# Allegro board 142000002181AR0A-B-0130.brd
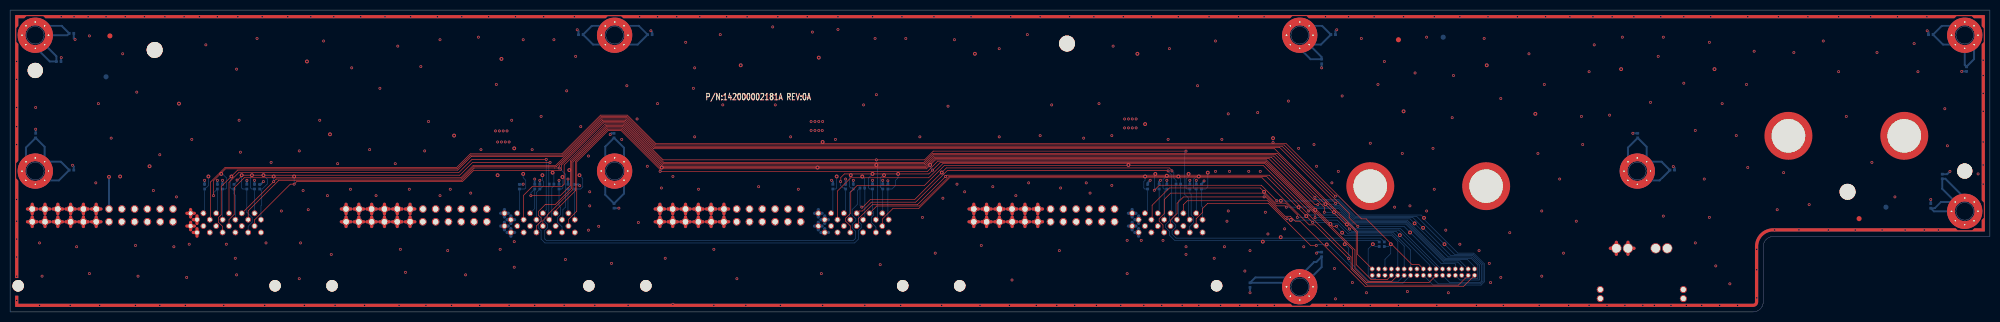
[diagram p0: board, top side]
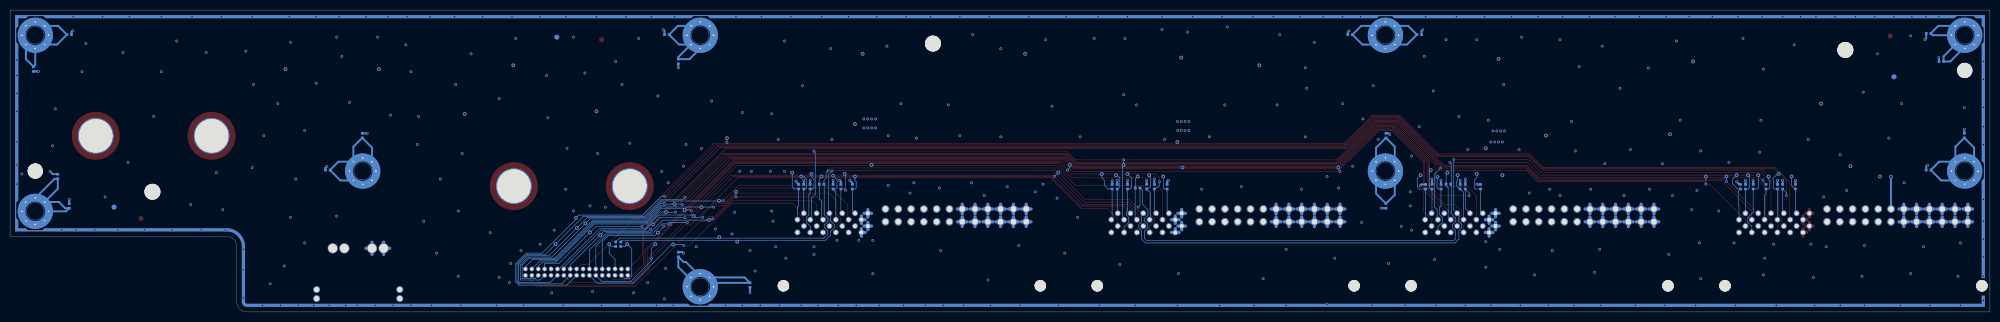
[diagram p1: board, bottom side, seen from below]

Outline 393 x 60 mm; copper layers: TOP, G2, V3, G4, V5, G6, V7, G8, V9, G10, V11, V12, G13, V14, G15, V16, G17, V18, G19, V20, G21, BOTTOM. Coordinates in mm from the lower left corner of the outline.

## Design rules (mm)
net group CLS_GND: nets GND_1 GND_2 GND_3 GND_4 GND_5 GND_6 GND_7 GND_8 GND_9
net group CLS_I2C: nets MB_PDU_SCL_R MB_PDU_SDA_R PDU_SCL PDU_SDA

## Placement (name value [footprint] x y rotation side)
C1  1000pF/50V  [CC0402]  12.19 55.37 270 bottom
C2  1000pF/50V  [CC0402]  113.28 55.12 90 bottom
C3  1000pF/50V  [CC0402]  127 55.12 270 bottom
C4  1000pF/50V  [CC0402]  262.64 55.12 270 bottom
C5  1000pF/50V  [CC0402]  381.25 55.12 90 bottom
C6  1000pF/50V  [CC0402]  9.65 49.78 270 bottom
C7  1000pF/50V  [CC0402]  260.35 49.78 180 bottom
C8  1000pF/50V  [CC0402]  388.37 48.26 180 bottom
C9  1000pF/50V  [CC0402]  5.08 35.05 0 bottom
C10  1000pF/50V  [CC0402]  119.89 35.05 0 bottom
C11  1000pF/50V  [CC0402]  323.09 35.05 0 bottom
C12  1000pF/50V  [CC0402]  12.19 28.19 270 bottom
C13  1000pF/50V  [CC0402]  329.95 28.19 270 bottom
C14  1000pF/50V  [CC0402]  383.54 26.92 0 bottom
C15  1000pF/50V  [CC0402]  119.89 21.08 180 bottom
C16  1000pF/50V  [CC0402]  381.25 21.08 0 bottom
C17  1000pF/50V  [CC0402]  260.35 11.43 0 bottom
C18  1000pF/50V  [CC0402]  246.13 5.33 180 bottom
CONN1  HI POWER  [CONN_2D54_48DP_54D25W_PIP_1]  27.1 5.2 180 bottom
CONN2  HI POWER  [CONN_2D54_48DP_54D25W_PIP_1]  89.4 5.2 180 bottom
CONN3  HI POWER  [CONN_2D54_48DP_54D25W_PIP_1]  151.7 5.2 180 bottom
CONN4  HI POWER  [CONN_2D54_48DP_54D25W_PIP_1]  214 5.2 180 bottom
CONN5  CONN_POWER_4P_G4  [CONN_2D3_4DP_18D2W12D3L_PIP]  323.9 12.65 0 bottom
CONN6  LCB25-G3424H01R-08  [CONN_1D27_2X17DP_90DEG_PIP]  280.54 7.9 0 bottom
H1  *SCREW_8_1  [MTH_276C138D_8DP]  5 55 0 top
H2  *SCREW_8_1  [MTH_276C138D_8DP]  120 55 0 top
H3  *SCREW_8_1  [MTH_276C138D_8DP]  256 55 0 top
H4  *SCREW_8_1  [MTH_276C138D_8DP]  388 55 0 top
H5  *SCREW_8_1  [MTH_276C138D_8DP]  5 28 0 top
H6  *SCREW_8_1  [MTH_276C138D_8DP]  120 28 0 top
H7  *SCREW_8_1  [MTH_276C138D_8DP]  323 28 0 top
H8  *SCREW_8_1  [MTH_276C138D_8DP]  388 20 0 top
H9  *SCREW_8_1  [MTH_276C138D_8DP]  256 5 0 top
NOREF  -  []  63.91 5.2 0 top
NOREF#2  -  []  270 25 0 top
NOREF#3  -  [unnamed#2]  275.59 54.1 0 top
NOREF#4  -  []  256 5 0 top
NOREF#5  -  []  388 20 0 top
NOREF#6  -  [unnamed#2]  367.03 18.54 0 top
NOREF#7  -  []  120 55 0 top
NOREF#8  -  [unnamed#2]  388 28 0 top
NOREF#9  -  []  388 55 0 top
NOREF#10  -  []  376 35 0 top
NOREF#11  -  []  353 35 0 top
NOREF#12  -  []  0 0 0 top
NOREF#13  -  []  393 15 0 top
NOREF#14  -  []  270 25 0 top
NOREF#15  -  []  293 25 0 top
NOREF#16  -  []  126.2 5.2 0 top
NOREF#17  -  []  5 48 0 top
NOREF#18  -  []  5 55 0 top
NOREF#19  -  []  323 28 0 top
NOREF#20  -  []  120 55 0 top
NOREF#21  -  []  388 55 0 top
NOREF#22  -  []  139.45 45.21 0 top
NOREF#23  -  []  1.61 5.2 0 top
NOREF#24  -  []  323 28 0 top
NOREF#25  -  []  256 55 0 top
NOREF#26  -  [unnamed#2]  364.74 23.88 0 top
NOREF#27  -  [unnamed#2]  5 48 0 top
NOREF#28  -  []  270.38 8.54 0 top
NOREF#29  -  [unnamed#2]  28.7 52.07 0 top
NOREF#30  -  []  0 0 0 top
NOREF#31  -  [unnamed#2]  19.81 54.86 0 top
NOREF#32  -  []  506.73 -44.45 0 top
NOREF#33  -  []  328.95 12.65 0 top
NOREF#34  -  []  0 0 0 top
NOREF#35  -  []  120 28 0 top
NOREF#36  -  []  188.51 5.2 0 top
NOREF#37  -  []  0 60 0 top
NOREF#38  -  []  320.74 -38.48 0 top
NOREF#39  -  []  0 0 0 top
NOREF#40  -  []  353 35 0 top
NOREF#41  -  []  270.38 7.27 0 top
NOREF#42  -  []  1.61 5.2 0 top
NOREF#43  -  [unnamed#2]  209.8 53.34 0 top
NOREF#44  -  []  328.95 12.65 0 top
NOREF#45  -  []  -40.64 -30.48 0 top
NOREF#46  -  [unnamed#2]  372.36 20.83 180 bottom
NOREF#47  -  [unnamed#2]  19.05 46.74 180 bottom
NOREF#48  -  [unnamed#2]  284.48 54.61 180 bottom
R1  33ohm  [RC0402]  107.49 25.4 90 bottom
R2  33ohm  [RC0402]  231.9 25.4 90 bottom
R3  0ohm  [RC0402]  38.61 24.89 180 bottom
R4  1Kohm  [RC0402]  41.15 24.89 180 bottom
R5  0ohm  [RC0402]  42.16 24.89 180 bottom
R6  33ohm  [RC0402]  44.45 24.89 0 bottom
R7  0ohm  [RC0402]  46.99 24.89 0 bottom
R8  0ohm  [RC0402]  48.51 24.89 180 bottom
R9  0ohm  [RC0402]  49.53 24.89 180 bottom
R10  0ohm  [RC0402]  101.09 24.89 180 bottom
R11  1Kohm  [RC0402]  104.14 24.89 180 bottom
R12  0ohm  [RC0402]  105.16 24.89 180 bottom
R13  0ohm  [RC0402]  108.97 24.89 0 bottom
R14  0ohm  [RC0402]  110.74 24.89 180 bottom
R15  0ohm  [RC0402]  112.01 24.89 180 bottom
R16  0ohm  [RC0402]  163.32 24.89 180 bottom
R17  1Kohm  [RC0402]  165.86 24.89 180 bottom
R18  0ohm  [RC0402]  167.39 24.89 180 bottom
R19  0ohm  [RC0402]  171.2 24.89 0 bottom
R20  0ohm  [RC0402]  173.23 24.89 180 bottom
R21  0ohm  [RC0402]  174.24 24.89 180 bottom
R22  0ohm  [RC0402]  225.81 24.89 180 bottom
R23  1Kohm  [RC0402]  228.09 24.89 180 bottom
R24  0ohm  [RC0402]  229.62 24.89 180 bottom
R25  0ohm  [RC0402]  234.19 24.89 0 bottom
R26  0ohm  [RC0402]  235.46 24.89 180 bottom
R27  0ohm  [RC0402]  236.47 24.89 180 bottom
R28  33ohm  [RC0402]  169.16 24.64 90 bottom
R29  0ohm  [RC0402]  271.78 13.46 180 bottom
R30  0ohm  [RC0402]  272.8 13.46 0 bottom
U1_PF  HI POWER  [GUIDE_PIN_1DP_9D53W15D14H]  353 35 0 top
U2_PF  HI POWER  [GUIDE_PIN_1DP_9D53W15D14H]  376 35 0 top
U3_PF  HI POWER  [GUIDE_PIN_1DP_9D53W15D14H]  270 25 0 top
U4_PF  HI POWER  [GUIDE_PIN_1DP_9D53W15D14H]  293 25 0 top

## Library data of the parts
C1-C18 = C_NP
CONN1-CONN4 = CONN_POWER_ALLTOP_DIP48_1
CONN5 = CONN_POWER_4P_G4
CONN6 = PIN HEADER_MALE_17PX2R
H1-H9 = SCREW_8_1
R1-R30 = R: tolerance: 1%
U1_PF U2_PF U3_PF U4_PF = GUIDE PIN_1P

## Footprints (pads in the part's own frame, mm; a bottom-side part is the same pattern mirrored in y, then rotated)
CC0402
  rect 0.559x0.539 smd: 1(0,0.454) 2(0,-0.454)
CONN_1D27_2X17DP_90DEG_PIP
  round 0.94 hole 0.61: 1(-10.16,-0.635) 2(-10.16,0.635) 3(-8.89,-0.635) 4(-8.89,0.635) 5(-7.62,-0.635) 6(-7.62,0.635) 7(-6.35,-0.635) 8(-6.35,0.635) 9(-5.08,-0.635) 10(-5.08,0.635) 11(-3.81,-0.635) 12(-3.81,0.635) 13(-2.54,-0.635) 14(-2.54,0.635) 15(-1.27,-0.635) 16(-1.27,0.635) 17(0,-0.635) 18(0,0.635) 19(1.27,-0.635) 20(1.27,0.635) 21(2.54,-0.635) 22(2.54,0.635) 23(3.81,-0.635) 24(3.81,0.635) 25(5.08,-0.635) 26(5.08,0.635) 27(6.35,-0.635) 28(6.35,0.635) 29(7.62,-0.635) 30(7.62,0.635) 31(8.89,-0.635) 32(8.89,0.635) 33(10.16,-0.635) 34(10.16,0.635)
CONN_2D3_4DP_18D2W12D3L_PIP
  round 1.397 hole 1.016: G1(-8.25,10) G2(-8.25,8.2) G3(8.25,10) G4(8.25,8.2)
  round 2.032 hole 1.702: P1(5.05,0) P2(2.75,0) P3(-2.75,0) P4(-5.05,0)
CONN_2D54_48DP_54D25W_PIP_1
  round 2.286 hole 2.286 unplated: (-25.495,0) (25.495,0)
  round 1.524 hole 1.092: P1-11(-5.235,15.26) P1-12(-2.695,15.26) P1-13(-0.155,15.26) P1-21(2.385,15.26) P1-22(4.925,15.26) P1-23(7.465,15.26) P2-11(10.005,15.26) P2-12(12.545,15.26) P2-13(15.085,15.26) P2-21(17.625,15.26) P2-22(20.165,15.26) P2-23(22.705,15.26) P3-11(-5.235,12.72) P3-12(-2.695,12.72) P3-13(-0.155,12.72) P3-21(2.385,12.72) P3-22(4.925,12.72) P3-23(7.465,12.72) P4-11(10.005,12.72) P4-12(12.545,12.72) P4-13(15.085,12.72) P4-21(17.625,12.72) P4-22(20.165,12.72) P4-23(22.705,12.72)
  round 1.143 hole 0.762: S1(-22.705,13.14) S2(-21.435,14.41) S3(-20.165,13.14) S4(-18.895,14.41) S5(-17.625,13.14) S6(-16.355,14.41) S7(-15.085,13.14) S8(-13.815,14.41) S9(-12.545,13.14) S10(-11.275,14.41) S11(-10.005,13.14) S12(-8.735,14.41) S13(-22.705,10.6) S14(-21.435,11.87) S15(-20.165,10.6) S16(-18.895,11.87) S17(-17.625,10.6) S18(-16.355,11.87) S19(-15.085,10.6) S20(-13.815,11.87) S21(-12.545,10.6) S22(-11.275,11.87) S23(-10.005,10.6) S24(-8.735,11.87)
GUIDE_PIN_1DP_9D53W15D14H
  round 9.525 hole 6.629: 1(0,0)
MTH_276C138D_8DP
  round 0 hole 3.505 unplated: (0,0)
  custom 0.407x0.407 hole 0.305: 1(0,2.629) 3(2.629,0) 5(0,-2.629) 7(-2.629,0)
  custom 0.407x0.407 hole 0.305 rot 135: 2(1.859,1.859) 6(-1.859,-1.859)
  custom 0.407x0.407 hole 0.305 rot 45: 4(1.859,-1.859) 8(-1.859,1.859)
RC0402
  rect 0.559x0.539 smd: 1(0,0.454) 2(0,-0.454)
unnamed#2
  round 1.016 smd: (0,0)

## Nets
GND: C1.2 C2.2 C3.2 C4.2 C5.2 C6.2 C7.2 C8.2 C9.2 C10.2 C11.2 C12.2 C13.2 C14.2 C15.2 C16.2 C17.2 C18.2 CONN1.P2-11 CONN1.P2-12 CONN1.P2-13 CONN1.P2-21 CONN1.P2-22 CONN1.P2-23 CONN1.P4-11 CONN1.P4-12 CONN1.P4-13 CONN1.P4-21 CONN1.P4-22 CONN1.P4-23 CONN2.P2-11 CONN2.P2-12 CONN2.P2-13 CONN2.P2-21 CONN2.P2-22 CONN2.P2-23 CONN2.P4-11 CONN2.P4-12 CONN2.P4-13 CONN2.P4-21 CONN2.P4-22 CONN2.P4-23 CONN3.P2-11 CONN3.P2-12 CONN3.P2-13 CONN3.P2-21 CONN3.P2-22 CONN3.P2-23 CONN3.P4-11 CONN3.P4-12 CONN3.P4-13 CONN3.P4-21 CONN3.P4-22 CONN3.P4-23 CONN4.P2-11 CONN4.P2-12 CONN4.P2-13 CONN4.P2-21 CONN4.P2-22 CONN4.P2-23 CONN4.P4-11 CONN4.P4-12 CONN4.P4-13 CONN4.P4-21 CONN4.P4-22 CONN4.P4-23 CONN5.P3(POWER_1N) CONN5.P4(POWER_2N) CONN6.2 CONN6.3 CONN6.6 CONN6.7 CONN6.15 CONN6.16 CONN6.25 CONN6.26 R3.1 R4.1 R5.1 R7.2 R8.1 R10.1 R11.1 R12.1 R13.2 R14.1 R16.1 R17.1 R18.1 R19.2 R20.1 R22.1 R23.1 R24.1 R25.2 R26.1 U2_PF.1 U4_PF.1
GND_1: C1.1 C6.1 H1.1 H1.2 H1.3 H1.4 H1.5 H1.6 H1.7 H1.8
GND_2: C9.1 C12.1 H5.1 H5.2 H5.3 H5.4 H5.5 H5.6 H5.7 H5.8
GND_3: C2.1 C3.1 H2.1 H2.2 H2.3 H2.4 H2.5 H2.6 H2.7 H2.8
GND_4: C11.1 C13.1 H7.1 H7.2 H7.3 H7.4 H7.5 H7.6 H7.7 H7.8
GND_5: C10.1 C15.1 H6.1 H6.2 H6.3 H6.4 H6.5 H6.6 H6.7 H6.8
GND_6: C4.1 C7.1 H3.1 H3.2 H3.3 H3.4 H3.5 H3.6 H3.7 H3.8
GND_7: C17.1 C18.1 H9.1 H9.2 H9.3 H9.4 H9.5 H9.6 H9.7 H9.8
GND_8: C14.1 C16.1 H8.1 H8.2 H8.3 H8.4 H8.5 H8.6 H8.7 H8.8
GND_9: C5.1 C8.1 H4.1 H4.2 H4.3 H4.4 H4.5 H4.6 H4.7 H4.8
MB_PDU_SCL_R: CONN6.4 R29.2
MB_PDU_SDA_R: CONN6.5 R30.1
PDU_12V: CONN1.P1-11 CONN1.P1-12 CONN1.P1-13 CONN1.P1-21 CONN1.P1-22 CONN1.P1-23 CONN1.P3-11 CONN1.P3-12 CONN1.P3-13 CONN1.P3-21 CONN1.P3-22 CONN1.P3-23 CONN2.P1-11 CONN2.P1-12 CONN2.P1-13 CONN2.P1-21 CONN2.P1-22 CONN2.P1-23 CONN2.P3-11 CONN2.P3-12 CONN2.P3-13 CONN2.P3-21 CONN2.P3-22 CONN2.P3-23 CONN3.P1-11 CONN3.P1-12 CONN3.P1-13 CONN3.P1-21 CONN3.P1-22 CONN3.P1-23 CONN3.P3-11 CONN3.P3-12 CONN3.P3-13 CONN3.P3-21 CONN3.P3-22 CONN3.P3-23 CONN4.P1-11 CONN4.P1-12 CONN4.P1-13 CONN4.P1-21 CONN4.P1-22 CONN4.P1-23 CONN4.P3-11 CONN4.P3-12 CONN4.P3-13 CONN4.P3-21 CONN4.P3-22 CONN4.P3-23 CONN5.P1(POWER_1P) CONN5.P2(POWER_2P) R9.1 R15.1 R21.1 R27.1 U1_PF.1 U3_PF.1
PDU_ISHARE: CONN1.S3 CONN2.S3 CONN3.S3 CONN4.S3
PDU_SCL: CONN1.S6 CONN2.S6 CONN3.S6 CONN4.S6 R29.1
PDU_SDA: R1.2 R2.2 R6.2 R28.2 R30.2
PS1_A0: CONN1.S15 R7.1
PS1_A1: CONN1.S10 R3.2
PS2_A0: CONN2.S15 R13.1
PS2_A1: CONN2.S10 R10.2
PS3_A0: CONN3.S15 R19.1
PS3_A1: CONN3.S10 R16.2
PS4_A0: CONN4.S15 R25.1
PS4_A1: CONN4.S10 R22.2
PSU1_12V_SENSE: CONN1.S1 R9.2
PSU1_ACOK_H: CONN1.S19 CONN6.27
PSU1_EEPROM_WP: CONN1.S18 CONN6.28
PSU1_PRESENT_L: CONN1.S14 CONN6.8
PSU1_PSKILL: CONN1.S7 R5.2
PSU1_PSON_L: CONN1.S8 CONN6.18 R4.2
PSU1_PWOK_H: CONN1.S9 CONN6.17
PSU1_RTN_SENSE: CONN1.S2 R8.2
PSU1_SDA: CONN1.S5 R6.1
PSU1_SMB_ALERT_L: CONN1.S4 CONN6.1
PSU2_12V_SENSE: CONN2.S1 R15.2
PSU2_ACOK_H: CONN2.S19 CONN6.29
PSU2_EEPROM_WP: CONN2.S18 CONN6.30
PSU2_PRESENT_L: CONN2.S14 CONN6.10
PSU2_PSKILL: CONN2.S7 R12.2
PSU2_PSON_L: CONN2.S8 CONN6.20 R11.2
PSU2_PWOK_H: CONN2.S9 CONN6.19
PSU2_RTN_SENSE: CONN2.S2 R14.2
PSU2_SDA: CONN2.S5 R1.1
PSU2_SMB_ALERT_L: CONN2.S4 CONN6.9
PSU3_12V_SENSE: CONN3.S1 R21.2
PSU3_ACOK_H: CONN3.S19 CONN6.31
PSU3_EEPROM_WP: CONN3.S18 CONN6.32
PSU3_PRESENT_L: CONN3.S14 CONN6.12
PSU3_PSKILL: CONN3.S7 R18.2
PSU3_PSON_L: CONN3.S8 CONN6.22 R17.2
PSU3_PWOK_H: CONN3.S9 CONN6.21
PSU3_RTN_SENSE: CONN3.S2 R20.2
PSU3_SDA: CONN3.S5 R28.1
PSU3_SMB_ALERT_L: CONN3.S4 CONN6.11
PSU4_12V_SENSE: CONN4.S1 R27.2
PSU4_ACOK_H: CONN4.S19 CONN6.33
PSU4_EEPROM_WP: CONN4.S18 CONN6.34
PSU4_PRESENT_L: CONN4.S14 CONN6.14
PSU4_PSKILL: CONN4.S7 R24.2
PSU4_PSON_L: CONN4.S8 CONN6.24 R23.2
PSU4_PWOK_H: CONN4.S9 CONN6.23
PSU4_RTN_SENSE: CONN4.S2 R26.2
PSU4_SDA: CONN4.S5 R2.1
PSU4_SMB_ALERT_L: CONN4.S4 CONN6.13
PSU_VSTB_3V3: CONN1.S11 CONN1.S12 CONN1.S23 CONN1.S24 CONN2.S11 CONN2.S12 CONN2.S23 CONN2.S24 CONN3.S11 CONN3.S12 CONN3.S23 CONN3.S24 CONN4.S11 CONN4.S12 CONN4.S23 CONN4.S24

Pads without a net: CONN1 S13 S16 S17 S20 S21 S22; CONN2 S13 S16 S17 S20 S21 S22; CONN3 S13 S16 S17 S20 S21 S22; CONN4 S13 S16 S17 S20 S21 S22; CONN5 G1 G2 G3 G4

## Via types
v1: diameter 0.762, hole 0.381, TOP to BOTTOM, 78 vias
v2: diameter 0.559, hole 0.305, TOP to BOTTOM, 513 vias

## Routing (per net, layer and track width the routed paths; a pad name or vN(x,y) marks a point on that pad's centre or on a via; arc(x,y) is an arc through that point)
GND: length 2287.9
  TOP w0.635: CONN2.P4-21 72.72,17.92 ; CONN2.P4-21 71.78,16.98 ; CONN2.P4-21 70.83,17.92 ; CONN2.P4-21 71.78,18.86 ; CONN4.P4-12 201.46,18.86 ; CONN4.P4-12 201.46,16.98 ; CONN4.P4-12 200.51,17.92 ; CONN4.P4-12 202.4,17.92 ; CONN3.P4-11 141.69,18.86 ; CONN3.P4-11 141.69,16.98 ; CONN3.P4-11 142.64,17.92 ; CONN3.P4-11 140.75,17.92 ; CONN2.P2-21 71.78,21.4 ; CONN2.P2-21 71.78,19.52 ; CONN2.P2-21 70.83,20.46 ; CONN2.P2-21 72.72,20.46 ; CONN4.P4-11 204,18.86 ; CONN4.P4-11 204,16.98 ; CONN4.P4-11 204.94,17.92 ; CONN4.P4-11 203.05,17.92 ; CONN4.P2-13 198.92,21.4 ; CONN4.P2-13 199.86,20.46 ; CONN4.P2-13 197.97,20.46 ; CONN4.P2-13 198.92,19.52 ; 192.89,20.46 CONN4.P2-22 ; CONN4.P2-22 193.84,21.4 ; CONN4.P2-22 194.78,20.46 ; CONN4.P2-22 193.84,19.52 ; 317.66,12.65 CONN5.P4 ; CONN5.P4 318.85,11.46 ; CONN5.P4 318.85,13.84 ; CONN3.P2-11 141.69,21.4 ; CONN3.P2-11 142.64,20.46 ; CONN3.P2-11 141.69,19.52 ; CONN3.P2-11 140.75,20.46 ; 8.53,17.92 CONN1.P4-21 ; CONN1.P4-21 9.47,16.98 ; CONN1.P4-21 9.47,18.86 ; CONN1.P4-21 10.42,17.92 ; 133.13,20.46 CONN3.P2-21 ; CONN3.P2-21 134.07,21.4 ; CONN3.P2-21 134.07,19.52 ; CONN3.P2-21 135.02,20.46 ; CONN2.P2-23 66.7,21.4 ; CONN2.P2-23 66.7,19.52 ; CONN2.P2-23 65.75,20.46 ; CONN2.P2-23 67.64,20.46 ; 65.75,17.92 CONN2.P4-23 ; CONN2.P4-23 66.7,16.98 ; CONN2.P4-23 67.64,17.92 ; CONN2.P4-23 66.7,18.86 ; CONN4.P4-22 193.84,18.86 ; CONN4.P4-22 194.78,17.92 ; CONN4.P4-22 192.89,17.92 ; CONN4.P4-22 193.84,16.98 ; CONN3.P2-12 140.1,20.46 ; CONN3.P2-12 138.21,20.46 ; CONN3.P2-12 139.15,21.4 ; CONN3.P2-12 139.15,19.52 ; 130.59,17.92 CONN3.P4-22 ; CONN3.P4-22 132.48,17.92 ; CONN3.P4-22 131.53,16.98 ; CONN3.P4-22 131.53,18.86 ; 4.39,16.98 CONN1.P4-23 ; CONN1.P4-23 5.34,17.92 ; CONN1.P4-23 4.39,18.86 ; CONN1.P4-23 3.45,17.92 ; 12.01,19.52 CONN1.P2-13 ; CONN1.P2-13 11.07,20.46 ; CONN1.P2-13 12.01,21.4 ; CONN1.P2-13 12.96,20.46 ; 128.05,20.46 CONN3.P2-23 ; CONN3.P2-23 128.99,19.52 ; CONN3.P2-23 129.94,20.46 ; CONN3.P2-23 128.99,21.4 ; CONN2.P2-12 76.86,21.4 ; CONN2.P2-12 77.8,20.46 ; CONN2.P2-12 76.86,19.52 ; CONN2.P2-12 75.91,20.46 ; CONN1.P2-21 9.47,21.4 ; CONN1.P2-21 8.53,20.46 ; CONN1.P2-21 9.47,19.52 ; CONN1.P2-21 10.42,20.46 ; CONN3.P2-13 136.61,21.4 ; CONN3.P2-13 135.67,20.46 ; CONN3.P2-13 136.61,19.52 ; CONN3.P2-13 137.56,20.46 ; CONN3.P4-21 135.02,17.92 ; CONN3.P4-21 134.07,16.98 ; CONN3.P4-21 134.07,18.86 ; CONN3.P4-21 133.13,17.92 ; 191.3,19.52 CONN4.P2-23 ; CONN4.P2-23 192.24,20.46 ; CONN4.P2-23 191.3,21.4 ; CONN4.P2-23 190.35,20.46 ; CONN4.P2-12 202.4,20.46 ; CONN4.P2-12 201.46,19.52 ; CONN4.P2-12 200.51,20.46 ; CONN4.P2-12 201.46,21.4 ; 195.43,20.46 CONN4.P2-21 ; CONN4.P2-21 197.32,20.46 ; CONN4.P2-21 196.38,19.52 ; CONN4.P2-21 196.38,21.4 ; 128.99,16.98 CONN3.P4-23 ; CONN3.P4-23 128.05,17.92 ; CONN3.P4-23 128.99,18.86 ; CONN3.P4-23 129.94,17.92 ; 74.32,19.52 CONN2.P2-13 ; CONN2.P2-13 74.32,21.4 ; CONN2.P2-13 73.37,20.46 ; CONN2.P2-13 75.26,20.46 ; CONN2.P4-13 74.32,18.86 ; CONN2.P4-13 75.26,17.92 ; CONN2.P4-13 74.32,16.98 ; CONN2.P4-13 73.37,17.92 ; 14.55,16.98 CONN1.P4-12 ; CONN1.P4-12 13.61,17.92 ; CONN1.P4-12 14.55,18.86 ; CONN1.P4-12 15.5,17.92 ; CONN4.P2-11 204.94,20.46 ; CONN4.P2-11 204,21.4 ; CONN4.P2-11 203.05,20.46 ; CONN4.P2-11 204,19.52 ; 69.24,19.52 CONN2.P2-22 ; CONN2.P2-22 68.29,20.46 ; CONN2.P2-22 70.18,20.46 ; CONN2.P2-22 69.24,21.4 ; CONN3.P2-22 132.48,20.46 ; CONN3.P2-22 131.53,21.4 ; CONN3.P2-22 131.53,19.52 ; CONN3.P2-22 130.59,20.46 ; 195.43,17.92 CONN4.P4-21 ; CONN4.P4-21 196.38,16.98 ; CONN4.P4-21 197.32,17.92 ; CONN4.P4-21 196.38,18.86 ; CONN4.P4-23 191.3,18.86 ; CONN4.P4-23 191.3,16.98 ; CONN4.P4-23 192.24,17.92 ; CONN4.P4-23 190.35,17.92 ; 12.01,16.98 CONN1.P4-13 ; CONN1.P4-13 12.01,18.86 ; CONN1.P4-13 11.07,17.92 ; CONN1.P4-13 12.96,17.92 ; CONN2.P4-11 80.34,17.92 ; CONN2.P4-11 79.4,18.86 ; CONN2.P4-11 78.45,17.92 ; CONN2.P4-11 79.4,16.98 ; CONN3.P4-12 139.15,18.86 ; CONN3.P4-12 138.21,17.92 ; CONN3.P4-12 140.1,17.92 ; CONN3.P4-12 139.15,16.98 ; 135.67,17.92 CONN3.P4-13 ; CONN3.P4-13 137.56,17.92 ; CONN3.P4-13 136.61,18.86 ; CONN3.P4-13 136.61,16.98 ; 4.39,19.52 CONN1.P2-23 ; CONN1.P2-23 3.45,20.46 ; CONN1.P2-23 4.39,21.4 ; CONN1.P2-23 5.34,20.46 ; 6.93,19.52 CONN1.P2-22 ; CONN1.P2-22 7.88,20.46 ; CONN1.P2-22 6.93,21.4 ; CONN1.P2-22 5.99,20.46 ; CONN2.P2-11 80.34,20.46 ; CONN2.P2-11 79.4,19.52 ; CONN2.P2-11 78.45,20.46 ; CONN2.P2-11 79.4,21.4 ; 321.15,11.46 CONN5.P3 ; CONN5.P3 321.15,13.84 ; CONN5.P3 322.34,12.65 ; 69.24,16.98 CONN2.P4-22 ; CONN2.P4-22 68.29,17.92 ; CONN2.P4-22 70.18,17.92 ; CONN2.P4-22 69.24,18.86 ; 5.99,17.92 CONN1.P4-22 ; CONN1.P4-22 6.93,18.86 ; CONN1.P4-22 7.88,17.92 ; CONN1.P4-22 6.93,16.98 ; 14.55,19.52 CONN1.P2-12 ; CONN1.P2-12 14.55,21.4 ; CONN1.P2-12 13.61,20.46 ; CONN1.P2-12 15.5,20.46 ; 76.86,16.98 CONN2.P4-12 ; CONN2.P4-12 77.8,17.92 ; CONN2.P4-12 76.86,18.86 ; CONN2.P4-12 75.91,17.92 ; 197.97,17.92 CONN4.P4-13 ; CONN4.P4-13 198.92,16.98 ; CONN4.P4-13 198.92,18.86 ; CONN4.P4-13 199.86,17.92 ; CONN1.P2-11 17.09,21.4 ; CONN1.P2-11 18.04,20.46 ; CONN1.P2-11 16.15,20.46 ; CONN1.P2-11 17.09,19.52 ; CONN1.P4-11 17.09,18.86 ; CONN1.P4-11 16.15,17.92 ; CONN1.P4-11 17.09,16.98 ; CONN1.P4-11 18.04,17.92
  G2 w0.635: CONN1.P4-23 4.39,18.86 ; CONN1.P4-23 3.45,17.92 ; CONN1.P4-23 5.34,17.92 ; CONN1.P4-23 4.39,16.98 ; CONN2.P4-12 77.8,17.92 ; CONN2.P4-12 76.86,18.86 ; CONN2.P4-12 75.91,17.92 ; CONN2.P4-12 76.86,16.98 ; CONN3.P2-11 142.64,20.46 ; CONN3.P2-11 141.69,19.52 ; CONN3.P2-11 140.75,20.46 ; CONN3.P2-11 141.69,21.4 ; CONN1.P2-12 15.5,20.46 ; CONN1.P2-12 14.55,19.52 ; CONN1.P2-12 14.55,21.4 ; CONN1.P2-12 13.61,20.46 ; 4.39,19.52 CONN1.P2-23 ; CONN1.P2-23 5.34,20.46 ; CONN1.P2-23 3.45,20.46 ; CONN1.P2-23 4.39,21.4 ; CONN1.P2-11 17.09,21.4 ; CONN1.P2-11 17.09,19.52 ; CONN1.P2-11 18.04,20.46 ; CONN1.P2-11 16.15,20.46 ; 71.78,16.98 CONN2.P4-21 ; CONN2.P4-21 72.72,17.92 ; CONN2.P4-21 70.83,17.92 ; CONN2.P4-21 71.78,18.86 ; 130.59,17.92 CONN3.P4-22 ; CONN3.P4-22 132.48,17.92 ; CONN3.P4-22 131.53,16.98 ; CONN3.P4-22 131.53,18.86 ; 198.92,16.98 CONN4.P4-13 ; CONN4.P4-13 198.92,18.86 ; CONN4.P4-13 199.86,17.92 ; CONN4.P4-13 197.97,17.92 ; 8.53,20.46 CONN1.P2-21 ; CONN1.P2-21 10.42,20.46 ; CONN1.P2-21 9.47,19.52 ; CONN1.P2-21 9.47,21.4 ; 5.99,17.92 CONN1.P4-22 ; CONN1.P4-22 7.88,17.92 ; CONN1.P4-22 6.93,16.98 ; CONN1.P4-22 6.93,18.86 ; CONN3.P2-23 128.99,21.4 ; CONN3.P2-23 128.05,20.46 ; CONN3.P2-23 128.99,19.52 ; CONN3.P2-23 129.94,20.46 ; 69.24,16.98 CONN2.P4-22 ; CONN2.P4-22 69.24,18.86 ; CONN2.P4-22 68.29,17.92 ; CONN2.P4-22 70.18,17.92 ; CONN4.P2-13 199.86,20.46 ; CONN4.P2-13 198.92,21.4 ; CONN4.P2-13 197.97,20.46 ; CONN4.P2-13 198.92,19.52 ; CONN1.P2-22 6.93,21.4 ; CONN1.P2-22 5.99,20.46 ; CONN1.P2-22 6.93,19.52 ; CONN1.P2-22 7.88,20.46 ; 73.37,17.92 CONN2.P4-13 ; CONN2.P4-13 74.32,18.86 ; CONN2.P4-13 75.26,17.92 ; CONN2.P4-13 74.32,16.98 ; 9.47,16.98 CONN1.P4-21 ; CONN1.P4-21 8.53,17.92 ; CONN1.P4-21 9.47,18.86 ; CONN1.P4-21 10.42,17.92 ; CONN4.P4-11 204.94,17.92 ; CONN4.P4-11 204,18.86 ; CONN4.P4-11 204,16.98 ; CONN4.P4-11 203.05,17.92 ; 195.43,17.92 CONN4.P4-21 ; CONN4.P4-21 196.38,16.98 ; CONN4.P4-21 196.38,18.86 ; CONN4.P4-21 197.32,17.92 ; CONN3.P2-21 135.02,20.46 ; CONN3.P2-21 133.13,20.46 ; CONN3.P2-21 134.07,21.4 ; CONN3.P2-21 134.07,19.52 ; 14.55,16.98 CONN1.P4-12 ; CONN1.P4-12 14.55,18.86 ; CONN1.P4-12 13.61,17.92 ; CONN1.P4-12 15.5,17.92 ; CONN3.P4-11 141.69,18.86 ; CONN3.P4-11 141.69,16.98 ; CONN3.P4-11 140.75,17.92 ; CONN3.P4-11 142.64,17.92 ; CONN4.P4-12 202.4,17.92 ; CONN4.P4-12 200.51,17.92 ; CONN4.P4-12 201.46,16.98 ; CONN4.P4-12 201.46,18.86 ; CONN2.P4-23 66.7,18.86 ; CONN2.P4-23 66.7,16.98 ; CONN2.P4-23 67.64,17.92 ; CONN2.P4-23 65.75,17.92 ; CONN2.P2-11 79.4,21.4 ; CONN2.P2-11 78.45,20.46 ; CONN2.P2-11 80.34,20.46 ; CONN2.P2-11 79.4,19.52 ; CONN2.P2-13 74.32,21.4 ; CONN2.P2-13 73.37,20.46 ; CONN2.P2-13 74.32,19.52 ; CONN2.P2-13 75.26,20.46 ; 11.07,20.46 CONN1.P2-13 ; CONN1.P2-13 12.96,20.46 ; CONN1.P2-13 12.01,19.52 ; CONN1.P2-13 12.01,21.4 ; 204,19.52 CONN4.P2-11 ; CONN4.P2-11 204,21.4 ; CONN4.P2-11 204.94,20.46 ; CONN4.P2-11 203.05,20.46 ; CONN4.P2-21 197.32,20.46 ; CONN4.P2-21 196.38,21.4 ; CONN4.P2-21 195.43,20.46 ; CONN4.P2-21 196.38,19.52 ; 128.99,16.98 CONN3.P4-23 ; CONN3.P4-23 128.05,17.92 ; CONN3.P4-23 129.94,17.92 ; CONN3.P4-23 128.99,18.86 ; 192.89,20.46 CONN4.P2-22 ; CONN4.P2-22 193.84,21.4 ; CONN4.P2-22 194.78,20.46 ; CONN4.P2-22 193.84,19.52 ; 65.75,20.46 CONN2.P2-23 ; CONN2.P2-23 66.7,19.52 ; CONN2.P2-23 66.7,21.4 ; CONN2.P2-23 67.64,20.46 ; 75.91,20.46 CONN2.P2-12 ; CONN2.P2-12 77.8,20.46 ; CONN2.P2-12 76.86,19.52 ; CONN2.P2-12 76.86,21.4 ; CONN4.P4-23 192.24,17.92 ; CONN4.P4-23 191.3,18.86 ; CONN4.P4-23 191.3,16.98 ; CONN4.P4-23 190.35,17.92 ; CONN4.P2-23 191.3,21.4 ; CONN4.P2-23 192.24,20.46 ; CONN4.P2-23 191.3,19.52 ; CONN4.P2-23 190.35,20.46 ; CONN3.P4-12 139.15,18.86 ; CONN3.P4-12 139.15,16.98 ; CONN3.P4-12 138.21,17.92 ; CONN3.P4-12 140.1,17.92 ; 318.85,11.46 CONN5.P4 ; CONN5.P4 317.66,12.65 ; CONN5.P4 318.85,13.84 ; CONN5.P3 321.15,13.84 ; CONN5.P3 321.15,11.46 ; CONN5.P3 322.34,12.65 ; CONN4.P2-12 202.4,20.46 ; CONN4.P2-12 200.51,20.46 ; CONN4.P2-12 201.46,19.52 ; CONN4.P2-12 201.46,21.4 ; 136.61,16.98 CONN3.P4-13 ; CONN3.P4-13 137.56,17.92 ; CONN3.P4-13 136.61,18.86 ; CONN3.P4-13 135.67,17.92 ; 134.07,16.98 CONN3.P4-21 ; CONN3.P4-21 134.07,18.86 ; CONN3.P4-21 135.02,17.92 ; CONN3.P4-21 133.13,17.92 ; 12.01,16.98 CONN1.P4-13 ; CONN1.P4-13 12.01,18.86 ; CONN1.P4-13 12.96,17.92 ; CONN1.P4-13 11.07,17.92 ; 192.89,17.92 CONN4.P4-22 ; CONN4.P4-22 193.84,16.98 ; CONN4.P4-22 194.78,17.92 ; CONN4.P4-22 193.84,18.86 ; CONN3.P2-12 140.1,20.46 ; CONN3.P2-12 139.15,21.4 ; CONN3.P2-12 139.15,19.52 ; CONN3.P2-12 138.21,20.46 ; 17.09,16.98 CONN1.P4-11 ; CONN1.P4-11 18.04,17.92 ; CONN1.P4-11 16.15,17.92 ; CONN1.P4-11 17.09,18.86 ; 78.45,17.92 CONN2.P4-11 ; CONN2.P4-11 80.34,17.92 ; CONN2.P4-11 79.4,18.86 ; CONN2.P4-11 79.4,16.98 ; 136.61,19.52 CONN3.P2-13 ; CONN3.P2-13 136.61,21.4 ; CONN3.P2-13 135.67,20.46 ; CONN3.P2-13 137.56,20.46 ; 130.59,20.46 CONN3.P2-22 ; CONN3.P2-22 131.53,21.4 ; CONN3.P2-22 132.48,20.46 ; CONN3.P2-22 131.53,19.52 ; 70.83,20.46 CONN2.P2-21 ; CONN2.P2-21 72.72,20.46 ; CONN2.P2-21 71.78,21.4 ; CONN2.P2-21 71.78,19.52 ; CONN2.P2-22 70.18,20.46 ; CONN2.P2-22 69.24,19.52 ; CONN2.P2-22 68.29,20.46 ; CONN2.P2-22 69.24,21.4
  G4 w0.635: CONN3.P2-22 131.53,21.4 ; CONN3.P2-22 131.53,19.52 ; CONN3.P2-22 132.48,20.46 ; CONN3.P2-22 130.59,20.46 ; 13.61,17.92 CONN1.P4-12 ; CONN1.P4-12 14.55,16.98 ; CONN1.P4-12 14.55,18.86 ; CONN1.P4-12 15.5,17.92 ; CONN1.P4-13 12.01,18.86 ; CONN1.P4-13 12.96,17.92 ; CONN1.P4-13 11.07,17.92 ; CONN1.P4-13 12.01,16.98 ; CONN3.P4-11 141.69,18.86 ; CONN3.P4-11 142.64,17.92 ; CONN3.P4-11 140.75,17.92 ; CONN3.P4-11 141.69,16.98 ; 6.93,16.98 CONN1.P4-22 ; CONN1.P4-22 6.93,18.86 ; CONN1.P4-22 7.88,17.92 ; CONN1.P4-22 5.99,17.92 ; CONN2.P2-11 79.4,21.4 ; CONN2.P2-11 79.4,19.52 ; CONN2.P2-11 78.45,20.46 ; CONN2.P2-11 80.34,20.46 ; 204,19.52 CONN4.P2-11 ; CONN4.P2-11 204.94,20.46 ; CONN4.P2-11 203.05,20.46 ; CONN4.P2-11 204,21.4 ; CONN1.P2-13 12.01,21.4 ; CONN1.P2-13 11.07,20.46 ; CONN1.P2-13 12.96,20.46 ; CONN1.P2-13 12.01,19.52 ; CONN3.P2-13 137.56,20.46 ; CONN3.P2-13 135.67,20.46 ; CONN3.P2-13 136.61,21.4 ; CONN3.P2-13 136.61,19.52 ; 198.92,19.52 CONN4.P2-13 ; CONN4.P2-13 197.97,20.46 ; CONN4.P2-13 198.92,21.4 ; CONN4.P2-13 199.86,20.46 ; 3.45,20.46 CONN1.P2-23 ; CONN1.P2-23 4.39,21.4 ; CONN1.P2-23 5.34,20.46 ; CONN1.P2-23 4.39,19.52 ; CONN1.P4-11 17.09,18.86 ; CONN1.P4-11 17.09,16.98 ; CONN1.P4-11 16.15,17.92 ; CONN1.P4-11 18.04,17.92 ; 17.09,19.52 CONN1.P2-11 ; CONN1.P2-11 16.15,20.46 ; CONN1.P2-11 17.09,21.4 ; CONN1.P2-11 18.04,20.46 ; CONN2.P4-23 67.64,17.92 ; CONN2.P4-23 66.7,16.98 ; CONN2.P4-23 65.75,17.92 ; CONN2.P4-23 66.7,18.86 ; CONN3.P4-22 131.53,18.86 ; CONN3.P4-22 130.59,17.92 ; CONN3.P4-22 132.48,17.92 ; CONN3.P4-22 131.53,16.98 ; CONN4.P2-23 191.3,21.4 ; CONN4.P2-23 190.35,20.46 ; CONN4.P2-23 191.3,19.52 ; CONN4.P2-23 192.24,20.46 ; CONN2.P2-22 70.18,20.46 ; CONN2.P2-22 68.29,20.46 ; CONN2.P2-22 69.24,19.52 ; CONN2.P2-22 69.24,21.4 ; 138.21,17.92 CONN3.P4-12 ; CONN3.P4-12 139.15,18.86 ; CONN3.P4-12 140.1,17.92 ; CONN3.P4-12 139.15,16.98 ; CONN5.P4 318.85,13.84 ; CONN5.P4 317.66,12.65 ; CONN5.P4 318.85,11.46 ; 192.89,17.92 CONN4.P4-22 ; CONN4.P4-22 193.84,18.86 ; CONN4.P4-22 193.84,16.98 ; CONN4.P4-22 194.78,17.92 ; CONN3.P4-21 134.07,18.86 ; CONN3.P4-21 134.07,16.98 ; CONN3.P4-21 135.02,17.92 ; CONN3.P4-21 133.13,17.92 ; 75.91,20.46 CONN2.P2-12 ; CONN2.P2-12 76.86,19.52 ; CONN2.P2-12 77.8,20.46 ; CONN2.P2-12 76.86,21.4 ; 200.51,20.46 CONN4.P2-12 ; CONN4.P2-12 201.46,21.4 ; CONN4.P2-12 201.46,19.52 ; CONN4.P2-12 202.4,20.46 ; CONN3.P2-21 135.02,20.46 ; CONN3.P2-21 134.07,19.52 ; CONN3.P2-21 134.07,21.4 ; CONN3.P2-21 133.13,20.46 ; CONN4.P2-21 196.38,21.4 ; CONN4.P2-21 196.38,19.52 ; CONN4.P2-21 197.32,20.46 ; CONN4.P2-21 195.43,20.46 ; CONN2.P2-23 67.64,20.46 ; CONN2.P2-23 66.7,19.52 ; CONN2.P2-23 65.75,20.46 ; CONN2.P2-23 66.7,21.4 ; CONN1.P2-21 10.42,20.46 ; CONN1.P2-21 9.47,19.52 ; CONN1.P2-21 9.47,21.4 ; CONN1.P2-21 8.53,20.46 ; 191.3,16.98 CONN4.P4-23 ; CONN4.P4-23 191.3,18.86 ; CONN4.P4-23 190.35,17.92 ; CONN4.P4-23 192.24,17.92 ; CONN3.P4-23 128.99,18.86 ; CONN3.P4-23 128.05,17.92 ; CONN3.P4-23 128.99,16.98 ; CONN3.P4-23 129.94,17.92 ; CONN2.P2-13 75.26,20.46 ; CONN2.P2-13 74.32,21.4 ; CONN2.P2-13 74.32,19.52 ; CONN2.P2-13 73.37,20.46 ; 204,16.98 CONN4.P4-11 ; CONN4.P4-11 204,18.86 ; CONN4.P4-11 203.05,17.92 ; CONN4.P4-11 204.94,17.92 ; CONN2.P4-12 77.8,17.92 ; CONN2.P4-12 76.86,16.98 ; CONN2.P4-12 75.91,17.92 ; CONN2.P4-12 76.86,18.86 ; CONN2.P4-11 80.34,17.92 ; CONN2.P4-11 79.4,18.86 ; CONN2.P4-11 78.45,17.92 ; CONN2.P4-11 79.4,16.98 ; 73.37,17.92 CONN2.P4-13 ; CONN2.P4-13 74.32,16.98 ; CONN2.P4-13 74.32,18.86 ; CONN2.P4-13 75.26,17.92 ; 3.45,17.92 CONN1.P4-23 ; CONN1.P4-23 4.39,16.98 ; CONN1.P4-23 5.34,17.92 ; CONN1.P4-23 4.39,18.86 ; CONN3.P2-12 140.1,20.46 ; CONN3.P2-12 139.15,19.52 ; CONN3.P2-12 138.21,20.46 ; CONN3.P2-12 139.15,21.4 ; CONN4.P2-22 194.78,20.46 ; CONN4.P2-22 193.84,21.4 ; CONN4.P2-22 192.89,20.46 ; CONN4.P2-22 193.84,19.52 ; 71.78,16.98 CONN2.P4-21 ; CONN2.P4-21 72.72,17.92 ; CONN2.P4-21 70.83,17.92 ; CONN2.P4-21 71.78,18.86 ; 5.99,20.46 CONN1.P2-22 ; CONN1.P2-22 6.93,19.52 ; CONN1.P2-22 7.88,20.46 ; CONN1.P2-22 6.93,21.4 ; CONN2.P2-21 71.78,21.4 ; CONN2.P2-21 70.83,20.46 ; CONN2.P2-21 72.72,20.46 ; CONN2.P2-21 71.78,19.52 ; 201.46,16.98 CONN4.P4-12 ; CONN4.P4-12 200.51,17.92 ; CONN4.P4-12 201.46,18.86 ; CONN4.P4-12 202.4,17.92 ; CONN2.P4-22 70.18,17.92 ; CONN2.P4-22 69.24,16.98 ; CONN2.P4-22 68.29,17.92 ; CONN2.P4-22 69.24,18.86 ; CONN3.P2-23 129.94,20.46 ; CONN3.P2-23 128.99,19.52 ; CONN3.P2-23 128.05,20.46 ; CONN3.P2-23 128.99,21.4 ; 198.92,16.98 CONN4.P4-13 ; CONN4.P4-13 199.86,17.92 ; CONN4.P4-13 198.92,18.86 ; CONN4.P4-13 197.97,17.92 ; 14.55,19.52 CONN1.P2-12 ; CONN1.P2-12 14.55,21.4 ; CONN1.P2-12 13.61,20.46 ; CONN1.P2-12 15.5,20.46 ; 9.47,16.98 CONN1.P4-21 ; CONN1.P4-21 10.42,17.92 ; CONN1.P4-21 8.53,17.92 ; CONN1.P4-21 9.47,18.86 ; 136.61,16.98 CONN3.P4-13 ; CONN3.P4-13 135.67,17.92 ; CONN3.P4-13 137.56,17.92 ; CONN3.P4-13 136.61,18.86 ; 195.43,17.92 CONN4.P4-21 ; CONN4.P4-21 196.38,16.98 ; CONN4.P4-21 197.32,17.92 ; CONN4.P4-21 196.38,18.86 ; CONN3.P2-11 142.64,20.46 ; CONN3.P2-11 141.69,19.52 ; CONN3.P2-11 141.69,21.4 ; CONN3.P2-11 140.75,20.46 ; CONN5.P3 321.15,13.84 ; CONN5.P3 322.34,12.65 ; CONN5.P3 321.15,11.46
  G6 w0.635: CONN4.P2-23 191.3,21.4 ; CONN4.P2-23 190.35,20.46 ; CONN4.P2-23 192.24,20.46 ; CONN4.P2-23 191.3,19.52 ; 130.59,17.92 CONN3.P4-22 ; CONN3.P4-22 132.48,17.92 ; CONN3.P4-22 131.53,16.98 ; CONN3.P4-22 131.53,18.86 ; 204,19.52 CONN4.P2-11 ; CONN4.P2-11 203.05,20.46 ; CONN4.P2-11 204,21.4 ; CONN4.P2-11 204.94,20.46 ; 134.07,19.52 CONN3.P2-21 ; CONN3.P2-21 135.02,20.46 ; CONN3.P2-21 134.07,21.4 ; CONN3.P2-21 133.13,20.46 ; 66.7,19.52 CONN2.P2-23 ; CONN2.P2-23 65.75,20.46 ; CONN2.P2-23 66.7,21.4 ; CONN2.P2-23 67.64,20.46 ; 141.69,19.52 CONN3.P2-11 ; CONN3.P2-11 141.69,21.4 ; CONN3.P2-11 142.64,20.46 ; CONN3.P2-11 140.75,20.46 ; CONN1.P4-23 5.34,17.92 ; CONN1.P4-23 3.45,17.92 ; CONN1.P4-23 4.39,16.98 ; CONN1.P4-23 4.39,18.86 ; 73.37,20.46 CONN2.P2-13 ; CONN2.P2-13 74.32,21.4 ; CONN2.P2-13 74.32,19.52 ; CONN2.P2-13 75.26,20.46 ; CONN2.P2-12 76.86,21.4 ; CONN2.P2-12 76.86,19.52 ; CONN2.P2-12 75.91,20.46 ; CONN2.P2-12 77.8,20.46 ; CONN1.P2-22 7.88,20.46 ; CONN1.P2-22 6.93,19.52 ; CONN1.P2-22 5.99,20.46 ; CONN1.P2-22 6.93,21.4 ; CONN1.P2-13 12.96,20.46 ; CONN1.P2-13 11.07,20.46 ; CONN1.P2-13 12.01,21.4 ; CONN1.P2-13 12.01,19.52 ; 74.32,16.98 CONN2.P4-13 ; CONN2.P4-13 73.37,17.92 ; CONN2.P4-13 75.26,17.92 ; CONN2.P4-13 74.32,18.86 ; 201.46,19.52 CONN4.P2-12 ; CONN4.P2-12 202.4,20.46 ; CONN4.P2-12 201.46,21.4 ; CONN4.P2-12 200.51,20.46 ; 79.4,16.98 CONN2.P4-11 ; CONN2.P4-11 79.4,18.86 ; CONN2.P4-11 80.34,17.92 ; CONN2.P4-11 78.45,17.92 ; 11.07,17.92 CONN1.P4-13 ; CONN1.P4-13 12.01,18.86 ; CONN1.P4-13 12.01,16.98 ; CONN1.P4-13 12.96,17.92 ; 198.92,19.52 CONN4.P2-13 ; CONN4.P2-13 197.97,20.46 ; CONN4.P2-13 198.92,21.4 ; CONN4.P2-13 199.86,20.46 ; CONN2.P4-12 76.86,18.86 ; CONN2.P4-12 75.91,17.92 ; CONN2.P4-12 76.86,16.98 ; CONN2.P4-12 77.8,17.92 ; CONN4.P4-23 192.24,17.92 ; CONN4.P4-23 190.35,17.92 ; CONN4.P4-23 191.3,16.98 ; CONN4.P4-23 191.3,18.86 ; CONN3.P2-23 128.99,21.4 ; CONN3.P2-23 128.99,19.52 ; CONN3.P2-23 129.94,20.46 ; CONN3.P2-23 128.05,20.46 ; CONN1.P2-21 10.42,20.46 ; CONN1.P2-21 9.47,19.52 ; CONN1.P2-21 8.53,20.46 ; CONN1.P2-21 9.47,21.4 ; CONN4.P4-12 202.4,17.92 ; CONN4.P4-12 200.51,17.92 ; CONN4.P4-12 201.46,18.86 ; CONN4.P4-12 201.46,16.98 ; CONN1.P4-12 14.55,18.86 ; CONN1.P4-12 15.5,17.92 ; CONN1.P4-12 14.55,16.98 ; CONN1.P4-12 13.61,17.92 ; CONN3.P4-13 137.56,17.92 ; CONN3.P4-13 136.61,16.98 ; CONN3.P4-13 136.61,18.86 ; CONN3.P4-13 135.67,17.92 ; 198.92,16.98 CONN4.P4-13 ; CONN4.P4-13 199.86,17.92 ; CONN4.P4-13 198.92,18.86 ; CONN4.P4-13 197.97,17.92 ; 135.67,20.46 CONN3.P2-13 ; CONN3.P2-13 136.61,21.4 ; CONN3.P2-13 136.61,19.52 ; CONN3.P2-13 137.56,20.46 ; CONN3.P2-12 140.1,20.46 ; CONN3.P2-12 139.15,21.4 ; CONN3.P2-12 139.15,19.52 ; CONN3.P2-12 138.21,20.46 ; CONN2.P2-22 70.18,20.46 ; CONN2.P2-22 69.24,19.52 ; CONN2.P2-22 69.24,21.4 ; CONN2.P2-22 68.29,20.46 ; 138.21,17.92 CONN3.P4-12 ; CONN3.P4-12 139.15,18.86 ; CONN3.P4-12 139.15,16.98 ; CONN3.P4-12 140.1,17.92 ; CONN3.P4-23 128.99,18.86 ; CONN3.P4-23 129.94,17.92 ; CONN3.P4-23 128.05,17.92 ; CONN3.P4-23 128.99,16.98 ; CONN4.P2-21 197.32,20.46 ; CONN4.P2-21 195.43,20.46 ; CONN4.P2-21 196.38,21.4 ; CONN4.P2-21 196.38,19.52 ; CONN2.P2-11 80.34,20.46 ; CONN2.P2-11 79.4,19.52 ; CONN2.P2-11 78.45,20.46 ; CONN2.P2-11 79.4,21.4 ; 65.75,17.92 CONN2.P4-23 ; CONN2.P4-23 67.64,17.92 ; CONN2.P4-23 66.7,18.86 ; CONN2.P4-23 66.7,16.98 ; CONN2.P2-21 72.72,20.46 ; CONN2.P2-21 71.78,21.4 ; CONN2.P2-21 70.83,20.46 ; CONN2.P2-21 71.78,19.52 ; 14.55,19.52 CONN1.P2-12 ; CONN1.P2-12 13.61,20.46 ; CONN1.P2-12 14.55,21.4 ; CONN1.P2-12 15.5,20.46 ; CONN1.P4-11 18.04,17.92 ; CONN1.P4-11 17.09,18.86 ; CONN1.P4-11 16.15,17.92 ; CONN1.P4-11 17.09,16.98 ; CONN4.P4-22 193.84,18.86 ; CONN4.P4-22 193.84,16.98 ; CONN4.P4-22 192.89,17.92 ; CONN4.P4-22 194.78,17.92 ; CONN1.P4-21 9.47,18.86 ; CONN1.P4-21 8.53,17.92 ; CONN1.P4-21 9.47,16.98 ; CONN1.P4-21 10.42,17.92 ; 204,16.98 CONN4.P4-11 ; CONN4.P4-11 203.05,17.92 ; CONN4.P4-11 204,18.86 ; CONN4.P4-11 204.94,17.92 ; CONN1.P2-23 5.34,20.46 ; CONN1.P2-23 3.45,20.46 ; CONN1.P2-23 4.39,21.4 ; CONN1.P2-23 4.39,19.52 ; CONN3.P4-21 134.07,18.86 ; CONN3.P4-21 135.02,17.92 ; CONN3.P4-21 133.13,17.92 ; CONN3.P4-21 134.07,16.98 ; 321.15,11.46 CONN5.P3 ; CONN5.P3 321.15,13.84 ; CONN5.P3 322.34,12.65 ; 130.59,20.46 CONN3.P2-22 ; CONN3.P2-22 131.53,21.4 ; CONN3.P2-22 132.48,20.46 ; CONN3.P2-22 131.53,19.52 ; CONN1.P4-22 6.93,18.86 ; CONN1.P4-22 7.88,17.92 ; CONN1.P4-22 6.93,16.98 ; CONN1.P4-22 5.99,17.92 ; 318.85,11.46 CONN5.P4 ; CONN5.P4 318.85,13.84 ; CONN5.P4 317.66,12.65 ; 141.69,16.98 CONN3.P4-11 ; CONN3.P4-11 142.64,17.92 ; CONN3.P4-11 141.69,18.86 ; CONN3.P4-11 140.75,17.92 ; CONN2.P4-22 69.24,18.86 ; CONN2.P4-22 70.18,17.92 ; CONN2.P4-22 69.24,16.98 ; CONN2.P4-22 68.29,17.92 ; CONN4.P2-22 193.84,21.4 ; CONN4.P2-22 194.78,20.46 ; CONN4.P2-22 192.89,20.46 ; CONN4.P2-22 193.84,19.52 ; CONN4.P4-21 197.32,17.92 ; CONN4.P4-21 195.43,17.92 ; CONN4.P4-21 196.38,16.98 ; CONN4.P4-21 196.38,18.86 ; 70.83,17.92 CONN2.P4-21 ; CONN2.P4-21 72.72,17.92 ; CONN2.P4-21 71.78,16.98 ; CONN2.P4-21 71.78,18.86 ; 16.15,20.46 CONN1.P2-11 ; CONN1.P2-11 17.09,19.52 ; CONN1.P2-11 17.09,21.4 ; CONN1.P2-11 18.04,20.46
  G8 w0.635: CONN2.P2-13 74.32,21.4 ; CONN2.P2-13 74.32,19.52 ; CONN2.P2-13 73.37,20.46 ; CONN2.P2-13 75.26,20.46 ; 128.05,17.92 CONN3.P4-23 ; CONN3.P4-23 128.99,18.86 ; CONN3.P4-23 128.99,16.98 ; CONN3.P4-23 129.94,17.92 ; CONN3.P2-21 134.07,21.4 ; CONN3.P2-21 135.02,20.46 ; CONN3.P2-21 134.07,19.52 ; CONN3.P2-21 133.13,20.46 ; CONN1.P4-22 7.88,17.92 ; CONN1.P4-22 5.99,17.92 ; CONN1.P4-22 6.93,16.98 ; CONN1.P4-22 6.93,18.86 ; CONN2.P4-13 75.26,17.92 ; CONN2.P4-13 74.32,16.98 ; CONN2.P4-13 74.32,18.86 ; CONN2.P4-13 73.37,17.92 ; CONN3.P2-13 136.61,21.4 ; CONN3.P2-13 135.67,20.46 ; CONN3.P2-13 136.61,19.52 ; CONN3.P2-13 137.56,20.46 ; 71.78,19.52 CONN2.P2-21 ; CONN2.P2-21 70.83,20.46 ; CONN2.P2-21 71.78,21.4 ; CONN2.P2-21 72.72,20.46 ; 8.53,17.92 CONN1.P4-21 ; CONN1.P4-21 10.42,17.92 ; CONN1.P4-21 9.47,16.98 ; CONN1.P4-21 9.47,18.86 ; CONN2.P4-11 80.34,17.92 ; CONN2.P4-11 79.4,18.86 ; CONN2.P4-11 78.45,17.92 ; CONN2.P4-11 79.4,16.98 ; CONN2.P4-23 66.7,18.86 ; CONN2.P4-23 66.7,16.98 ; CONN2.P4-23 67.64,17.92 ; CONN2.P4-23 65.75,17.92 ; 13.61,20.46 CONN1.P2-12 ; CONN1.P2-12 15.5,20.46 ; CONN1.P2-12 14.55,21.4 ; CONN1.P2-12 14.55,19.52 ; 130.59,20.46 CONN3.P2-22 ; CONN3.P2-22 131.53,21.4 ; CONN3.P2-22 132.48,20.46 ; CONN3.P2-22 131.53,19.52 ; 5.99,20.46 CONN1.P2-22 ; CONN1.P2-22 6.93,21.4 ; CONN1.P2-22 7.88,20.46 ; CONN1.P2-22 6.93,19.52 ; 140.75,20.46 CONN3.P2-11 ; CONN3.P2-11 141.69,21.4 ; CONN3.P2-11 141.69,19.52 ; CONN3.P2-11 142.64,20.46 ; CONN4.P4-21 197.32,17.92 ; CONN4.P4-21 196.38,16.98 ; CONN4.P4-21 196.38,18.86 ; CONN4.P4-21 195.43,17.92 ; CONN4.P4-11 204,18.86 ; CONN4.P4-11 203.05,17.92 ; CONN4.P4-11 204.94,17.92 ; CONN4.P4-11 204,16.98 ; CONN4.P4-13 198.92,18.86 ; CONN4.P4-13 199.86,17.92 ; CONN4.P4-13 198.92,16.98 ; CONN4.P4-13 197.97,17.92 ; 68.29,20.46 CONN2.P2-22 ; CONN2.P2-22 69.24,21.4 ; CONN2.P2-22 69.24,19.52 ; CONN2.P2-22 70.18,20.46 ; 190.35,20.46 CONN4.P2-23 ; CONN4.P2-23 191.3,19.52 ; CONN4.P2-23 192.24,20.46 ; CONN4.P2-23 191.3,21.4 ; 8.53,20.46 CONN1.P2-21 ; CONN1.P2-21 10.42,20.46 ; CONN1.P2-21 9.47,21.4 ; CONN1.P2-21 9.47,19.52 ; 65.75,20.46 CONN2.P2-23 ; CONN2.P2-23 66.7,19.52 ; CONN2.P2-23 67.64,20.46 ; CONN2.P2-23 66.7,21.4 ; CONN2.P4-12 76.86,18.86 ; CONN2.P4-12 75.91,17.92 ; CONN2.P4-12 76.86,16.98 ; CONN2.P4-12 77.8,17.92 ; 4.39,16.98 CONN1.P4-23 ; CONN1.P4-23 3.45,17.92 ; CONN1.P4-23 4.39,18.86 ; CONN1.P4-23 5.34,17.92 ; CONN3.P4-12 139.15,18.86 ; CONN3.P4-12 140.1,17.92 ; CONN3.P4-12 138.21,17.92 ; CONN3.P4-12 139.15,16.98 ; CONN1.P4-13 12.01,18.86 ; CONN1.P4-13 12.96,17.92 ; CONN1.P4-13 11.07,17.92 ; CONN1.P4-13 12.01,16.98 ; CONN3.P4-11 141.69,18.86 ; CONN3.P4-11 142.64,17.92 ; CONN3.P4-11 141.69,16.98 ; CONN3.P4-11 140.75,17.92 ; 76.86,19.52 CONN2.P2-12 ; CONN2.P2-12 75.91,20.46 ; CONN2.P2-12 76.86,21.4 ; CONN2.P2-12 77.8,20.46 ; 79.4,19.52 CONN2.P2-11 ; CONN2.P2-11 78.45,20.46 ; CONN2.P2-11 80.34,20.46 ; CONN2.P2-11 79.4,21.4 ; CONN4.P4-22 194.78,17.92 ; CONN4.P4-22 193.84,16.98 ; CONN4.P4-22 193.84,18.86 ; CONN4.P4-22 192.89,17.92 ; CONN4.P2-13 199.86,20.46 ; CONN4.P2-13 198.92,19.52 ; CONN4.P2-13 197.97,20.46 ; CONN4.P2-13 198.92,21.4 ; 16.15,17.92 CONN1.P4-11 ; CONN1.P4-11 17.09,18.86 ; CONN1.P4-11 17.09,16.98 ; CONN1.P4-11 18.04,17.92 ; CONN3.P4-21 135.02,17.92 ; CONN3.P4-21 134.07,18.86 ; CONN3.P4-21 133.13,17.92 ; CONN3.P4-21 134.07,16.98 ; 196.38,19.52 CONN4.P2-21 ; CONN4.P2-21 195.43,20.46 ; CONN4.P2-21 196.38,21.4 ; CONN4.P2-21 197.32,20.46 ; CONN3.P2-12 140.1,20.46 ; CONN3.P2-12 139.15,21.4 ; CONN3.P2-12 139.15,19.52 ; CONN3.P2-12 138.21,20.46 ; 128.05,20.46 CONN3.P2-23 ; CONN3.P2-23 129.94,20.46 ; CONN3.P2-23 128.99,21.4 ; CONN3.P2-23 128.99,19.52 ; CONN2.P4-21 71.78,18.86 ; CONN2.P4-21 71.78,16.98 ; CONN2.P4-21 70.83,17.92 ; CONN2.P4-21 72.72,17.92 ; 193.84,19.52 CONN4.P2-22 ; CONN4.P2-22 194.78,20.46 ; CONN4.P2-22 193.84,21.4 ; CONN4.P2-22 192.89,20.46 ; CONN5.P4 318.85,13.84 ; CONN5.P4 318.85,11.46 ; CONN5.P4 317.66,12.65 ; CONN3.P4-13 136.61,18.86 ; CONN3.P4-13 137.56,17.92 ; CONN3.P4-13 135.67,17.92 ; CONN3.P4-13 136.61,16.98 ; 201.46,19.52 CONN4.P2-12 ; CONN4.P2-12 201.46,21.4 ; CONN4.P2-12 200.51,20.46 ; CONN4.P2-12 202.4,20.46 ; 4.39,19.52 CONN1.P2-23 ; CONN1.P2-23 3.45,20.46 ; CONN1.P2-23 4.39,21.4 ; CONN1.P2-23 5.34,20.46 ; 68.29,17.92 CONN2.P4-22 ; CONN2.P4-22 70.18,17.92 ; CONN2.P4-22 69.24,18.86 ; CONN2.P4-22 69.24,16.98 ; 191.3,16.98 CONN4.P4-23 ; CONN4.P4-23 190.35,17.92 ; CONN4.P4-23 192.24,17.92 ; CONN4.P4-23 191.3,18.86 ; 201.46,16.98 CONN4.P4-12 ; CONN4.P4-12 201.46,18.86 ; CONN4.P4-12 202.4,17.92 ; CONN4.P4-12 200.51,17.92 ; 204,19.52 CONN4.P2-11 ; CONN4.P2-11 204,21.4 ; CONN4.P2-11 204.94,20.46 ; CONN4.P2-11 203.05,20.46 ; CONN1.P4-12 14.55,18.86 ; CONN1.P4-12 13.61,17.92 ; CONN1.P4-12 14.55,16.98 ; CONN1.P4-12 15.5,17.92 ; CONN5.P3 322.34,12.65 ; CONN5.P3 321.15,13.84 ; CONN5.P3 321.15,11.46 ; CONN3.P4-22 132.48,17.92 ; CONN3.P4-22 131.53,16.98 ; CONN3.P4-22 130.59,17.92 ; CONN3.P4-22 131.53,18.86 ; CONN1.P2-11 18.04,20.46 ; CONN1.P2-11 16.15,20.46 ; CONN1.P2-11 17.09,19.52 ; CONN1.P2-11 17.09,21.4 ; CONN1.P2-13 12.01,21.4 ; CONN1.P2-13 12.01,19.52 ; CONN1.P2-13 11.07,20.46 ; CONN1.P2-13 12.96,20.46
  G10 w0.635: CONN5.P3 322.34,12.65 ; CONN5.P3 321.15,13.84 ; CONN5.P3 321.15,11.46 ; CONN1.P2-22 6.93,21.4 ; CONN1.P2-22 5.99,20.46 ; CONN1.P2-22 6.93,19.52 ; CONN1.P2-22 7.88,20.46 ; CONN1.P2-13 12.96,20.46 ; CONN1.P2-13 11.07,20.46 ; CONN1.P2-13 12.01,21.4 ; CONN1.P2-13 12.01,19.52 ; CONN1.P4-11 17.09,18.86 ; CONN1.P4-11 18.04,17.92 ; CONN1.P4-11 16.15,17.92 ; CONN1.P4-11 17.09,16.98 ; CONN1.P2-11 18.04,20.46 ; CONN1.P2-11 16.15,20.46 ; CONN1.P2-11 17.09,19.52 ; CONN1.P2-11 17.09,21.4 ; CONN2.P4-11 80.34,17.92 ; CONN2.P4-11 79.4,16.98 ; CONN2.P4-11 79.4,18.86 ; CONN2.P4-11 78.45,17.92 ; CONN3.P2-13 137.56,20.46 ; CONN3.P2-13 136.61,19.52 ; CONN3.P2-13 136.61,21.4 ; CONN3.P2-13 135.67,20.46 ; CONN1.P2-21 9.47,21.4 ; CONN1.P2-21 9.47,19.52 ; CONN1.P2-21 10.42,20.46 ; CONN1.P2-21 8.53,20.46 ; 131.53,16.98 CONN3.P4-22 ; CONN3.P4-22 131.53,18.86 ; CONN3.P4-22 130.59,17.92 ; CONN3.P4-22 132.48,17.92 ; CONN4.P4-23 192.24,17.92 ; CONN4.P4-23 191.3,18.86 ; CONN4.P4-23 190.35,17.92 ; CONN4.P4-23 191.3,16.98 ; 198.92,16.98 CONN4.P4-13 ; CONN4.P4-13 197.97,17.92 ; CONN4.P4-13 198.92,18.86 ; CONN4.P4-13 199.86,17.92 ; CONN4.P2-11 204,21.4 ; CONN4.P2-11 204.94,20.46 ; CONN4.P2-11 204,19.52 ; CONN4.P2-11 203.05,20.46 ; CONN1.P4-23 5.34,17.92 ; CONN1.P4-23 4.39,16.98 ; CONN1.P4-23 4.39,18.86 ; CONN1.P4-23 3.45,17.92 ; 8.53,17.92 CONN1.P4-21 ; CONN1.P4-21 9.47,16.98 ; CONN1.P4-21 9.47,18.86 ; CONN1.P4-21 10.42,17.92 ; 204,16.98 CONN4.P4-11 ; CONN4.P4-11 204.94,17.92 ; CONN4.P4-11 203.05,17.92 ; CONN4.P4-11 204,18.86 ; CONN3.P4-11 142.64,17.92 ; CONN3.P4-11 140.75,17.92 ; CONN3.P4-11 141.69,18.86 ; CONN3.P4-11 141.69,16.98 ; 140.75,20.46 CONN3.P2-11 ; CONN3.P2-11 142.64,20.46 ; CONN3.P2-11 141.69,21.4 ; CONN3.P2-11 141.69,19.52 ; CONN3.P4-23 128.99,18.86 ; CONN3.P4-23 129.94,17.92 ; CONN3.P4-23 128.05,17.92 ; CONN3.P4-23 128.99,16.98 ; CONN2.P4-13 75.26,17.92 ; CONN2.P4-13 73.37,17.92 ; CONN2.P4-13 74.32,16.98 ; CONN2.P4-13 74.32,18.86 ; 193.84,16.98 CONN4.P4-22 ; CONN4.P4-22 194.78,17.92 ; CONN4.P4-22 193.84,18.86 ; CONN4.P4-22 192.89,17.92 ; 134.07,16.98 CONN3.P4-21 ; CONN3.P4-21 134.07,18.86 ; CONN3.P4-21 133.13,17.92 ; CONN3.P4-21 135.02,17.92 ; 196.38,16.98 CONN4.P4-21 ; CONN4.P4-21 196.38,18.86 ; CONN4.P4-21 195.43,17.92 ; CONN4.P4-21 197.32,17.92 ; CONN4.P4-12 202.4,17.92 ; CONN4.P4-12 201.46,16.98 ; CONN4.P4-12 201.46,18.86 ; CONN4.P4-12 200.51,17.92 ; CONN2.P2-12 77.8,20.46 ; CONN2.P2-12 76.86,21.4 ; CONN2.P2-12 76.86,19.52 ; CONN2.P2-12 75.91,20.46 ; 197.97,20.46 CONN4.P2-13 ; CONN4.P2-13 198.92,21.4 ; CONN4.P2-13 199.86,20.46 ; CONN4.P2-13 198.92,19.52 ; CONN3.P4-13 137.56,17.92 ; CONN3.P4-13 135.67,17.92 ; CONN3.P4-13 136.61,18.86 ; CONN3.P4-13 136.61,16.98 ; 12.01,16.98 CONN1.P4-13 ; CONN1.P4-13 12.96,17.92 ; CONN1.P4-13 11.07,17.92 ; CONN1.P4-13 12.01,18.86 ; CONN1.P2-23 4.39,21.4 ; CONN1.P2-23 5.34,20.46 ; CONN1.P2-23 3.45,20.46 ; CONN1.P2-23 4.39,19.52 ; CONN2.P2-21 72.72,20.46 ; CONN2.P2-21 71.78,21.4 ; CONN2.P2-21 71.78,19.52 ; CONN2.P2-21 70.83,20.46 ; CONN2.P2-22 69.24,21.4 ; CONN2.P2-22 70.18,20.46 ; CONN2.P2-22 69.24,19.52 ; CONN2.P2-22 68.29,20.46 ; 6.93,16.98 CONN1.P4-22 ; CONN1.P4-22 5.99,17.92 ; CONN1.P4-22 6.93,18.86 ; CONN1.P4-22 7.88,17.92 ; 79.4,19.52 CONN2.P2-11 ; CONN2.P2-11 78.45,20.46 ; CONN2.P2-11 80.34,20.46 ; CONN2.P2-11 79.4,21.4 ; 130.59,20.46 CONN3.P2-22 ; CONN3.P2-22 131.53,21.4 ; CONN3.P2-22 132.48,20.46 ; CONN3.P2-22 131.53,19.52 ; CONN2.P4-21 72.72,17.92 ; CONN2.P4-21 71.78,18.86 ; CONN2.P4-21 70.83,17.92 ; CONN2.P4-21 71.78,16.98 ; CONN1.P2-12 14.55,21.4 ; CONN1.P2-12 14.55,19.52 ; CONN1.P2-12 13.61,20.46 ; CONN1.P2-12 15.5,20.46 ; CONN3.P2-12 140.1,20.46 ; CONN3.P2-12 138.21,20.46 ; CONN3.P2-12 139.15,19.52 ; CONN3.P2-12 139.15,21.4 ; CONN3.P2-21 135.02,20.46 ; CONN3.P2-21 134.07,21.4 ; CONN3.P2-21 133.13,20.46 ; CONN3.P2-21 134.07,19.52 ; 65.75,20.46 CONN2.P2-23 ; CONN2.P2-23 67.64,20.46 ; CONN2.P2-23 66.7,21.4 ; CONN2.P2-23 66.7,19.52 ; CONN2.P4-12 76.86,18.86 ; CONN2.P4-12 75.91,17.92 ; CONN2.P4-12 77.8,17.92 ; CONN2.P4-12 76.86,16.98 ; CONN2.P2-13 75.26,20.46 ; CONN2.P2-13 74.32,19.52 ; CONN2.P2-13 73.37,20.46 ; CONN2.P2-13 74.32,21.4 ; CONN4.P2-12 201.46,21.4 ; CONN4.P2-12 201.46,19.52 ; CONN4.P2-12 200.51,20.46 ; CONN4.P2-12 202.4,20.46 ; CONN5.P4 318.85,13.84 ; CONN5.P4 317.66,12.65 ; CONN5.P4 318.85,11.46 ; CONN4.P2-23 191.3,21.4 ; CONN4.P2-23 192.24,20.46 ; CONN4.P2-23 190.35,20.46 ; CONN4.P2-23 191.3,19.52 ; CONN2.P4-22 70.18,17.92 ; CONN2.P4-22 69.24,16.98 ; CONN2.P4-22 69.24,18.86 ; CONN2.P4-22 68.29,17.92 ; 13.61,17.92 CONN1.P4-12 ; CONN1.P4-12 14.55,18.86 ; CONN1.P4-12 15.5,17.92 ; CONN1.P4-12 14.55,16.98 ; CONN4.P2-22 193.84,21.4 ; CONN4.P2-22 193.84,19.52 ; CONN4.P2-22 194.78,20.46 ; CONN4.P2-22 192.89,20.46 ; CONN4.P2-21 196.38,21.4 ; CONN4.P2-21 197.32,20.46 ; CONN4.P2-21 195.43,20.46 ; CONN4.P2-21 196.38,19.52 ; 66.7,16.98 CONN2.P4-23 ; CONN2.P4-23 65.75,17.92 ; CONN2.P4-23 66.7,18.86 ; CONN2.P4-23 67.64,17.92 ; 128.05,20.46 CONN3.P2-23 ; CONN3.P2-23 128.99,19.52 ; CONN3.P2-23 129.94,20.46 ; CONN3.P2-23 128.99,21.4 ; CONN3.P4-12 140.1,17.92 ; CONN3.P4-12 139.15,18.86 ; CONN3.P4-12 139.15,16.98 ; CONN3.P4-12 138.21,17.92
  G13 w0.635: CONN5.P4 318.85,13.84 ; CONN5.P4 318.85,11.46 ; CONN5.P4 317.66,12.65 ; CONN3.P4-23 128.99,18.86 ; CONN3.P4-23 129.94,17.92 ; CONN3.P4-23 128.99,16.98 ; CONN3.P4-23 128.05,17.92 ; 74.32,16.98 CONN2.P4-13 ; CONN2.P4-13 75.26,17.92 ; CONN2.P4-13 74.32,18.86 ; CONN2.P4-13 73.37,17.92 ; 191.3,19.52 CONN4.P2-23 ; CONN4.P2-23 191.3,21.4 ; CONN4.P2-23 192.24,20.46 ; CONN4.P2-23 190.35,20.46 ; CONN4.P4-22 194.78,17.92 ; CONN4.P4-22 193.84,16.98 ; CONN4.P4-22 192.89,17.92 ; CONN4.P4-22 193.84,18.86 ; CONN4.P4-13 198.92,18.86 ; CONN4.P4-13 197.97,17.92 ; CONN4.P4-13 198.92,16.98 ; CONN4.P4-13 199.86,17.92 ; CONN1.P4-11 18.04,17.92 ; CONN1.P4-11 17.09,16.98 ; CONN1.P4-11 16.15,17.92 ; CONN1.P4-11 17.09,18.86 ; CONN4.P2-21 196.38,21.4 ; CONN4.P2-21 196.38,19.52 ; CONN4.P2-21 195.43,20.46 ; CONN4.P2-21 197.32,20.46 ; CONN4.P2-11 204,21.4 ; CONN4.P2-11 203.05,20.46 ; CONN4.P2-11 204,19.52 ; CONN4.P2-11 204.94,20.46 ; CONN1.P2-23 4.39,21.4 ; CONN1.P2-23 3.45,20.46 ; CONN1.P2-23 5.34,20.46 ; CONN1.P2-23 4.39,19.52 ; CONN2.P2-12 77.8,20.46 ; CONN2.P2-12 76.86,21.4 ; CONN2.P2-12 76.86,19.52 ; CONN2.P2-12 75.91,20.46 ; CONN1.P4-23 5.34,17.92 ; CONN1.P4-23 3.45,17.92 ; CONN1.P4-23 4.39,18.86 ; CONN1.P4-23 4.39,16.98 ; CONN2.P4-12 77.8,17.92 ; CONN2.P4-12 76.86,18.86 ; CONN2.P4-12 75.91,17.92 ; CONN2.P4-12 76.86,16.98 ; CONN1.P2-11 17.09,21.4 ; CONN1.P2-11 18.04,20.46 ; CONN1.P2-11 17.09,19.52 ; CONN1.P2-11 16.15,20.46 ; CONN3.P4-21 135.02,17.92 ; CONN3.P4-21 134.07,18.86 ; CONN3.P4-21 133.13,17.92 ; CONN3.P4-21 134.07,16.98 ; CONN5.P3 322.34,12.65 ; CONN5.P3 321.15,13.84 ; CONN5.P3 321.15,11.46 ; CONN4.P4-21 196.38,18.86 ; CONN4.P4-21 197.32,17.92 ; CONN4.P4-21 196.38,16.98 ; CONN4.P4-21 195.43,17.92 ; 128.99,19.52 CONN3.P2-23 ; CONN3.P2-23 129.94,20.46 ; CONN3.P2-23 128.99,21.4 ; CONN3.P2-23 128.05,20.46 ; CONN4.P2-13 198.92,21.4 ; CONN4.P2-13 198.92,19.52 ; CONN4.P2-13 199.86,20.46 ; CONN4.P2-13 197.97,20.46 ; CONN2.P2-23 67.64,20.46 ; CONN2.P2-23 66.7,19.52 ; CONN2.P2-23 66.7,21.4 ; CONN2.P2-23 65.75,20.46 ; CONN3.P2-13 136.61,21.4 ; CONN3.P2-13 136.61,19.52 ; CONN3.P2-13 135.67,20.46 ; CONN3.P2-13 137.56,20.46 ; CONN1.P2-22 7.88,20.46 ; CONN1.P2-22 6.93,21.4 ; CONN1.P2-22 5.99,20.46 ; CONN1.P2-22 6.93,19.52 ; CONN4.P4-23 192.24,17.92 ; CONN4.P4-23 191.3,18.86 ; CONN4.P4-23 191.3,16.98 ; CONN4.P4-23 190.35,17.92 ; 130.59,17.92 CONN3.P4-22 ; CONN3.P4-22 132.48,17.92 ; CONN3.P4-22 131.53,18.86 ; CONN3.P4-22 131.53,16.98 ; 139.15,16.98 CONN3.P4-12 ; CONN3.P4-12 138.21,17.92 ; CONN3.P4-12 140.1,17.92 ; CONN3.P4-12 139.15,18.86 ; 141.69,19.52 CONN3.P2-11 ; CONN3.P2-11 142.64,20.46 ; CONN3.P2-11 140.75,20.46 ; CONN3.P2-11 141.69,21.4 ; 5.99,17.92 CONN1.P4-22 ; CONN1.P4-22 6.93,18.86 ; CONN1.P4-22 6.93,16.98 ; CONN1.P4-22 7.88,17.92 ; 139.15,19.52 CONN3.P2-12 ; CONN3.P2-12 140.1,20.46 ; CONN3.P2-12 138.21,20.46 ; CONN3.P2-12 139.15,21.4 ; 71.78,16.98 CONN2.P4-21 ; CONN2.P4-21 70.83,17.92 ; CONN2.P4-21 71.78,18.86 ; CONN2.P4-21 72.72,17.92 ; CONN3.P2-21 134.07,21.4 ; CONN3.P2-21 135.02,20.46 ; CONN3.P2-21 133.13,20.46 ; CONN3.P2-21 134.07,19.52 ; CONN4.P2-12 201.46,21.4 ; CONN4.P2-12 201.46,19.52 ; CONN4.P2-12 202.4,20.46 ; CONN4.P2-12 200.51,20.46 ; 78.45,20.46 CONN2.P2-11 ; CONN2.P2-11 80.34,20.46 ; CONN2.P2-11 79.4,19.52 ; CONN2.P2-11 79.4,21.4 ; 8.53,17.92 CONN1.P4-21 ; CONN1.P4-21 9.47,18.86 ; CONN1.P4-21 10.42,17.92 ; CONN1.P4-21 9.47,16.98 ; CONN2.P2-13 75.26,20.46 ; CONN2.P2-13 74.32,21.4 ; CONN2.P2-13 74.32,19.52 ; CONN2.P2-13 73.37,20.46 ; 13.61,17.92 CONN1.P4-12 ; CONN1.P4-12 14.55,16.98 ; CONN1.P4-12 15.5,17.92 ; CONN1.P4-12 14.55,18.86 ; CONN2.P4-11 79.4,18.86 ; CONN2.P4-11 80.34,17.92 ; CONN2.P4-11 79.4,16.98 ; CONN2.P4-11 78.45,17.92 ; 11.07,17.92 CONN1.P4-13 ; CONN1.P4-13 12.01,18.86 ; CONN1.P4-13 12.96,17.92 ; CONN1.P4-13 12.01,16.98 ; CONN2.P4-23 67.64,17.92 ; CONN2.P4-23 66.7,16.98 ; CONN2.P4-23 66.7,18.86 ; CONN2.P4-23 65.75,17.92 ; CONN2.P2-21 72.72,20.46 ; CONN2.P2-21 71.78,21.4 ; CONN2.P2-21 71.78,19.52 ; CONN2.P2-21 70.83,20.46 ; CONN3.P4-11 141.69,18.86 ; CONN3.P4-11 140.75,17.92 ; CONN3.P4-11 142.64,17.92 ; CONN3.P4-11 141.69,16.98 ; CONN1.P2-21 9.47,21.4 ; CONN1.P2-21 9.47,19.52 ; CONN1.P2-21 10.42,20.46 ; CONN1.P2-21 8.53,20.46 ; 135.67,17.92 CONN3.P4-13 ; CONN3.P4-13 136.61,18.86 ; CONN3.P4-13 136.61,16.98 ; CONN3.P4-13 137.56,17.92 ; 131.53,19.52 CONN3.P2-22 ; CONN3.P2-22 130.59,20.46 ; CONN3.P2-22 132.48,20.46 ; CONN3.P2-22 131.53,21.4 ; CONN4.P4-11 204.94,17.92 ; CONN4.P4-11 204,18.86 ; CONN4.P4-11 203.05,17.92 ; CONN4.P4-11 204,16.98 ; 69.24,19.52 CONN2.P2-22 ; CONN2.P2-22 69.24,21.4 ; CONN2.P2-22 70.18,20.46 ; CONN2.P2-22 68.29,20.46 ; 69.24,16.98 CONN2.P4-22 ; CONN2.P4-22 70.18,17.92 ; CONN2.P4-22 68.29,17.92 ; CONN2.P4-22 69.24,18.86 ; CONN1.P2-12 14.55,21.4 ; CONN1.P2-12 14.55,19.52 ; CONN1.P2-12 13.61,20.46 ; CONN1.P2-12 15.5,20.46 ; CONN4.P4-12 202.4,17.92 ; CONN4.P4-12 200.51,17.92 ; CONN4.P4-12 201.46,18.86 ; CONN4.P4-12 201.46,16.98 ; CONN1.P2-13 12.01,21.4 ; CONN1.P2-13 12.01,19.52 ; CONN1.P2-13 12.96,20.46 ; CONN1.P2-13 11.07,20.46 ; CONN4.P2-22 193.84,21.4 ; CONN4.P2-22 193.84,19.52 ; CONN4.P2-22 194.78,20.46 ; CONN4.P2-22 192.89,20.46
  G15 w0.635: CONN2.P2-13 74.32,21.4 ; CONN2.P2-13 73.37,20.46 ; CONN2.P2-13 75.26,20.46 ; CONN2.P2-13 74.32,19.52 ; 76.86,19.52 CONN2.P2-12 ; CONN2.P2-12 77.8,20.46 ; CONN2.P2-12 75.91,20.46 ; CONN2.P2-12 76.86,21.4 ; CONN4.P4-23 191.3,18.86 ; CONN4.P4-23 192.24,17.92 ; CONN4.P4-23 191.3,16.98 ; CONN4.P4-23 190.35,17.92 ; CONN1.P2-23 4.39,21.4 ; CONN1.P2-23 3.45,20.46 ; CONN1.P2-23 4.39,19.52 ; CONN1.P2-23 5.34,20.46 ; 197.97,17.92 CONN4.P4-13 ; CONN4.P4-13 198.92,16.98 ; CONN4.P4-13 198.92,18.86 ; CONN4.P4-13 199.86,17.92 ; CONN3.P4-13 136.61,18.86 ; CONN3.P4-13 135.67,17.92 ; CONN3.P4-13 136.61,16.98 ; CONN3.P4-13 137.56,17.92 ; 201.46,19.52 CONN4.P2-12 ; CONN4.P2-12 201.46,21.4 ; CONN4.P2-12 202.4,20.46 ; CONN4.P2-12 200.51,20.46 ; 8.53,17.92 CONN1.P4-21 ; CONN1.P4-21 10.42,17.92 ; CONN1.P4-21 9.47,18.86 ; CONN1.P4-21 9.47,16.98 ; 16.15,17.92 CONN1.P4-11 ; CONN1.P4-11 18.04,17.92 ; CONN1.P4-11 17.09,16.98 ; CONN1.P4-11 17.09,18.86 ; CONN2.P2-23 67.64,20.46 ; CONN2.P2-23 66.7,21.4 ; CONN2.P2-23 66.7,19.52 ; CONN2.P2-23 65.75,20.46 ; 9.47,19.52 CONN1.P2-21 ; CONN1.P2-21 10.42,20.46 ; CONN1.P2-21 9.47,21.4 ; CONN1.P2-21 8.53,20.46 ; CONN4.P4-11 204.94,17.92 ; CONN4.P4-11 203.05,17.92 ; CONN4.P4-11 204,16.98 ; CONN4.P4-11 204,18.86 ; 128.99,19.52 CONN3.P2-23 ; CONN3.P2-23 128.05,20.46 ; CONN3.P2-23 129.94,20.46 ; CONN3.P2-23 128.99,21.4 ; 73.37,17.92 CONN2.P4-13 ; CONN2.P4-13 75.26,17.92 ; CONN2.P4-13 74.32,16.98 ; CONN2.P4-13 74.32,18.86 ; 191.3,19.52 CONN4.P2-23 ; CONN4.P2-23 191.3,21.4 ; CONN4.P2-23 190.35,20.46 ; CONN4.P2-23 192.24,20.46 ; CONN1.P4-13 12.96,17.92 ; CONN1.P4-13 12.01,18.86 ; CONN1.P4-13 12.01,16.98 ; CONN1.P4-13 11.07,17.92 ; CONN4.P4-21 197.32,17.92 ; CONN4.P4-21 196.38,16.98 ; CONN4.P4-21 195.43,17.92 ; CONN4.P4-21 196.38,18.86 ; CONN4.P2-13 199.86,20.46 ; CONN4.P2-13 197.97,20.46 ; CONN4.P2-13 198.92,19.52 ; CONN4.P2-13 198.92,21.4 ; CONN5.P4 318.85,13.84 ; CONN5.P4 318.85,11.46 ; CONN5.P4 317.66,12.65 ; CONN4.P2-22 194.78,20.46 ; CONN4.P2-22 193.84,19.52 ; CONN4.P2-22 193.84,21.4 ; CONN4.P2-22 192.89,20.46 ; CONN2.P4-23 66.7,18.86 ; CONN2.P4-23 67.64,17.92 ; CONN2.P4-23 65.75,17.92 ; CONN2.P4-23 66.7,16.98 ; CONN2.P2-11 80.34,20.46 ; CONN2.P2-11 78.45,20.46 ; CONN2.P2-11 79.4,19.52 ; CONN2.P2-11 79.4,21.4 ; CONN2.P4-11 80.34,17.92 ; CONN2.P4-11 78.45,17.92 ; CONN2.P4-11 79.4,18.86 ; CONN2.P4-11 79.4,16.98 ; CONN5.P3 321.15,13.84 ; CONN5.P3 321.15,11.46 ; CONN5.P3 322.34,12.65 ; 140.75,17.92 CONN3.P4-11 ; CONN3.P4-11 142.64,17.92 ; CONN3.P4-11 141.69,18.86 ; CONN3.P4-11 141.69,16.98 ; 70.83,17.92 CONN2.P4-21 ; CONN2.P4-21 72.72,17.92 ; CONN2.P4-21 71.78,18.86 ; CONN2.P4-21 71.78,16.98 ; CONN1.P2-22 7.88,20.46 ; CONN1.P2-22 6.93,19.52 ; CONN1.P2-22 5.99,20.46 ; CONN1.P2-22 6.93,21.4 ; 69.24,19.52 CONN2.P2-22 ; CONN2.P2-22 70.18,20.46 ; CONN2.P2-22 69.24,21.4 ; CONN2.P2-22 68.29,20.46 ; CONN1.P4-23 4.39,18.86 ; CONN1.P4-23 3.45,17.92 ; CONN1.P4-23 5.34,17.92 ; CONN1.P4-23 4.39,16.98 ; 141.69,19.52 CONN3.P2-11 ; CONN3.P2-11 141.69,21.4 ; CONN3.P2-11 142.64,20.46 ; CONN3.P2-11 140.75,20.46 ; 204,19.52 CONN4.P2-11 ; CONN4.P2-11 203.05,20.46 ; CONN4.P2-11 204.94,20.46 ; CONN4.P2-11 204,21.4 ; CONN3.P2-22 132.48,20.46 ; CONN3.P2-22 131.53,19.52 ; CONN3.P2-22 130.59,20.46 ; CONN3.P2-22 131.53,21.4 ; CONN2.P4-12 77.8,17.92 ; CONN2.P4-12 75.91,17.92 ; CONN2.P4-12 76.86,18.86 ; CONN2.P4-12 76.86,16.98 ; 134.07,19.52 CONN3.P2-21 ; CONN3.P2-21 135.02,20.46 ; CONN3.P2-21 134.07,21.4 ; CONN3.P2-21 133.13,20.46 ; CONN1.P4-22 6.93,18.86 ; CONN1.P4-22 6.93,16.98 ; CONN1.P4-22 7.88,17.92 ; CONN1.P4-22 5.99,17.92 ; 128.99,16.98 CONN3.P4-23 ; CONN3.P4-23 128.05,17.92 ; CONN3.P4-23 128.99,18.86 ; CONN3.P4-23 129.94,17.92 ; CONN1.P2-13 12.01,21.4 ; CONN1.P2-13 11.07,20.46 ; CONN1.P2-13 12.96,20.46 ; CONN1.P2-13 12.01,19.52 ; 70.83,20.46 CONN2.P2-21 ; CONN2.P2-21 71.78,19.52 ; CONN2.P2-21 71.78,21.4 ; CONN2.P2-21 72.72,20.46 ; 133.13,17.92 CONN3.P4-21 ; CONN3.P4-21 134.07,18.86 ; CONN3.P4-21 134.07,16.98 ; CONN3.P4-21 135.02,17.92 ; CONN3.P2-12 139.15,21.4 ; CONN3.P2-12 140.1,20.46 ; CONN3.P2-12 138.21,20.46 ; CONN3.P2-12 139.15,19.52 ; CONN1.P2-11 17.09,21.4 ; CONN1.P2-11 17.09,19.52 ; CONN1.P2-11 18.04,20.46 ; CONN1.P2-11 16.15,20.46 ; CONN4.P4-12 201.46,18.86 ; CONN4.P4-12 202.4,17.92 ; CONN4.P4-12 200.51,17.92 ; CONN4.P4-12 201.46,16.98 ; CONN3.P2-13 136.61,21.4 ; CONN3.P2-13 135.67,20.46 ; CONN3.P2-13 136.61,19.52 ; CONN3.P2-13 137.56,20.46 ; 13.61,20.46 CONN1.P2-12 ; CONN1.P2-12 15.5,20.46 ; CONN1.P2-12 14.55,19.52 ; CONN1.P2-12 14.55,21.4 ; CONN4.P2-21 197.32,20.46 ; CONN4.P2-21 196.38,19.52 ; CONN4.P2-21 195.43,20.46 ; CONN4.P2-21 196.38,21.4 ; 130.59,17.92 CONN3.P4-22 ; CONN3.P4-22 131.53,18.86 ; CONN3.P4-22 132.48,17.92 ; CONN3.P4-22 131.53,16.98 ; 13.61,17.92 CONN1.P4-12 ; CONN1.P4-12 14.55,18.86 ; CONN1.P4-12 14.55,16.98 ; CONN1.P4-12 15.5,17.92 ; 193.84,16.98 CONN4.P4-22 ; CONN4.P4-22 192.89,17.92 ; CONN4.P4-22 194.78,17.92 ; CONN4.P4-22 193.84,18.86 ; 139.15,16.98 CONN3.P4-12 ; CONN3.P4-12 139.15,18.86 ; CONN3.P4-12 138.21,17.92 ; CONN3.P4-12 140.1,17.92 ; 68.29,17.92 CONN2.P4-22 ; CONN2.P4-22 69.24,16.98 ; CONN2.P4-22 69.24,18.86 ; CONN2.P4-22 70.18,17.92
  G17 w0.635: CONN4.P4-11 204.94,17.92 ; CONN4.P4-11 203.05,17.92 ; CONN4.P4-11 204,18.86 ; CONN4.P4-11 204,16.98 ; 131.53,19.52 CONN3.P2-22 ; CONN3.P2-22 131.53,21.4 ; CONN3.P2-22 130.59,20.46 ; CONN3.P2-22 132.48,20.46 ; 196.38,16.98 CONN4.P4-21 ; CONN4.P4-21 197.32,17.92 ; CONN4.P4-21 195.43,17.92 ; CONN4.P4-21 196.38,18.86 ; CONN3.P4-22 131.53,18.86 ; CONN3.P4-22 132.48,17.92 ; CONN3.P4-22 131.53,16.98 ; CONN3.P4-22 130.59,17.92 ; CONN4.P2-12 202.4,20.46 ; CONN4.P2-12 201.46,19.52 ; CONN4.P2-12 200.51,20.46 ; CONN4.P2-12 201.46,21.4 ; 5.99,17.92 CONN1.P4-22 ; CONN1.P4-22 6.93,16.98 ; CONN1.P4-22 7.88,17.92 ; CONN1.P4-22 6.93,18.86 ; CONN2.P4-12 76.86,18.86 ; CONN2.P4-12 75.91,17.92 ; CONN2.P4-12 76.86,16.98 ; CONN2.P4-12 77.8,17.92 ; CONN3.P4-12 139.15,18.86 ; CONN3.P4-12 138.21,17.92 ; CONN3.P4-12 139.15,16.98 ; CONN3.P4-12 140.1,17.92 ; 8.53,20.46 CONN1.P2-21 ; CONN1.P2-21 9.47,19.52 ; CONN1.P2-21 10.42,20.46 ; CONN1.P2-21 9.47,21.4 ; CONN1.P2-12 15.5,20.46 ; CONN1.P2-12 13.61,20.46 ; CONN1.P2-12 14.55,19.52 ; CONN1.P2-12 14.55,21.4 ; 198.92,16.98 CONN4.P4-13 ; CONN4.P4-13 197.97,17.92 ; CONN4.P4-13 198.92,18.86 ; CONN4.P4-13 199.86,17.92 ; CONN1.P4-12 14.55,18.86 ; CONN1.P4-12 13.61,17.92 ; CONN1.P4-12 14.55,16.98 ; CONN1.P4-12 15.5,17.92 ; 133.13,20.46 CONN3.P2-21 ; CONN3.P2-21 134.07,21.4 ; CONN3.P2-21 134.07,19.52 ; CONN3.P2-21 135.02,20.46 ; 201.46,16.98 CONN4.P4-12 ; CONN4.P4-12 200.51,17.92 ; CONN4.P4-12 202.4,17.92 ; CONN4.P4-12 201.46,18.86 ; 128.99,16.98 CONN3.P4-23 ; CONN3.P4-23 128.05,17.92 ; CONN3.P4-23 129.94,17.92 ; CONN3.P4-23 128.99,18.86 ; CONN3.P2-23 129.94,20.46 ; CONN3.P2-23 128.05,20.46 ; CONN3.P2-23 128.99,19.52 ; CONN3.P2-23 128.99,21.4 ; CONN4.P2-22 193.84,21.4 ; CONN4.P2-22 194.78,20.46 ; CONN4.P2-22 192.89,20.46 ; CONN4.P2-22 193.84,19.52 ; 3.45,17.92 CONN1.P4-23 ; CONN1.P4-23 4.39,16.98 ; CONN1.P4-23 4.39,18.86 ; CONN1.P4-23 5.34,17.92 ; CONN2.P2-11 80.34,20.46 ; CONN2.P2-11 79.4,21.4 ; CONN2.P2-11 79.4,19.52 ; CONN2.P2-11 78.45,20.46 ; CONN4.P2-21 197.32,20.46 ; CONN4.P2-21 196.38,21.4 ; CONN4.P2-21 196.38,19.52 ; CONN4.P2-21 195.43,20.46 ; CONN4.P2-11 204,21.4 ; CONN4.P2-11 204.94,20.46 ; CONN4.P2-11 204,19.52 ; CONN4.P2-11 203.05,20.46 ; 65.75,17.92 CONN2.P4-23 ; CONN2.P4-23 66.7,16.98 ; CONN2.P4-23 67.64,17.92 ; CONN2.P4-23 66.7,18.86 ; CONN1.P2-11 17.09,21.4 ; CONN1.P2-11 16.15,20.46 ; CONN1.P2-11 17.09,19.52 ; CONN1.P2-11 18.04,20.46 ; 17.09,16.98 CONN1.P4-11 ; CONN1.P4-11 18.04,17.92 ; CONN1.P4-11 16.15,17.92 ; CONN1.P4-11 17.09,18.86 ; 70.83,17.92 CONN2.P4-21 ; CONN2.P4-21 71.78,16.98 ; CONN2.P4-21 71.78,18.86 ; CONN2.P4-21 72.72,17.92 ; CONN1.P4-13 12.96,17.92 ; CONN1.P4-13 11.07,17.92 ; CONN1.P4-13 12.01,18.86 ; CONN1.P4-13 12.01,16.98 ; 140.75,20.46 CONN3.P2-11 ; CONN3.P2-11 141.69,19.52 ; CONN3.P2-11 142.64,20.46 ; CONN3.P2-11 141.69,21.4 ; 136.61,19.52 CONN3.P2-13 ; CONN3.P2-13 136.61,21.4 ; CONN3.P2-13 135.67,20.46 ; CONN3.P2-13 137.56,20.46 ; CONN2.P2-13 75.26,20.46 ; CONN2.P2-13 74.32,19.52 ; CONN2.P2-13 74.32,21.4 ; CONN2.P2-13 73.37,20.46 ; 4.39,19.52 CONN1.P2-23 ; CONN1.P2-23 4.39,21.4 ; CONN1.P2-23 5.34,20.46 ; CONN1.P2-23 3.45,20.46 ; CONN1.P4-21 9.47,18.86 ; CONN1.P4-21 9.47,16.98 ; CONN1.P4-21 10.42,17.92 ; CONN1.P4-21 8.53,17.92 ; CONN4.P2-23 191.3,21.4 ; CONN4.P2-23 190.35,20.46 ; CONN4.P2-23 192.24,20.46 ; CONN4.P2-23 191.3,19.52 ; CONN5.P4 318.85,13.84 ; CONN5.P4 317.66,12.65 ; CONN5.P4 318.85,11.46 ; 69.24,16.98 CONN2.P4-22 ; CONN2.P4-22 69.24,18.86 ; CONN2.P4-22 68.29,17.92 ; CONN2.P4-22 70.18,17.92 ; 65.75,20.46 CONN2.P2-23 ; CONN2.P2-23 66.7,19.52 ; CONN2.P2-23 67.64,20.46 ; CONN2.P2-23 66.7,21.4 ; 12.01,19.52 CONN1.P2-13 ; CONN1.P2-13 11.07,20.46 ; CONN1.P2-13 12.01,21.4 ; CONN1.P2-13 12.96,20.46 ; 76.86,19.52 CONN2.P2-12 ; CONN2.P2-12 75.91,20.46 ; CONN2.P2-12 77.8,20.46 ; CONN2.P2-12 76.86,21.4 ; 192.89,17.92 CONN4.P4-22 ; CONN4.P4-22 194.78,17.92 ; CONN4.P4-22 193.84,18.86 ; CONN4.P4-22 193.84,16.98 ; 133.13,17.92 CONN3.P4-21 ; CONN3.P4-21 134.07,16.98 ; CONN3.P4-21 134.07,18.86 ; CONN3.P4-21 135.02,17.92 ; CONN5.P3 322.34,12.65 ; CONN5.P3 321.15,11.46 ; CONN5.P3 321.15,13.84 ; 6.93,19.52 CONN1.P2-22 ; CONN1.P2-22 5.99,20.46 ; CONN1.P2-22 6.93,21.4 ; CONN1.P2-22 7.88,20.46 ; CONN3.P4-13 136.61,18.86 ; CONN3.P4-13 135.67,17.92 ; CONN3.P4-13 137.56,17.92 ; CONN3.P4-13 136.61,16.98 ; CONN4.P4-23 191.3,18.86 ; CONN4.P4-23 190.35,17.92 ; CONN4.P4-23 192.24,17.92 ; CONN4.P4-23 191.3,16.98 ; 78.45,17.92 CONN2.P4-11 ; CONN2.P4-11 79.4,16.98 ; CONN2.P4-11 80.34,17.92 ; CONN2.P4-11 79.4,18.86 ; CONN2.P2-21 71.78,21.4 ; CONN2.P2-21 71.78,19.52 ; CONN2.P2-21 70.83,20.46 ; CONN2.P2-21 72.72,20.46 ; CONN4.P2-13 198.92,21.4 ; CONN4.P2-13 199.86,20.46 ; CONN4.P2-13 197.97,20.46 ; CONN4.P2-13 198.92,19.52 ; CONN2.P4-13 74.32,18.86 ; CONN2.P4-13 74.32,16.98 ; CONN2.P4-13 73.37,17.92 ; CONN2.P4-13 75.26,17.92 ; 141.69,16.98 CONN3.P4-11 ; CONN3.P4-11 141.69,18.86 ; CONN3.P4-11 142.64,17.92 ; CONN3.P4-11 140.75,17.92 ; CONN3.P2-12 139.15,21.4 ; CONN3.P2-12 139.15,19.52 ; CONN3.P2-12 140.1,20.46 ; CONN3.P2-12 138.21,20.46 ; CONN2.P2-22 70.18,20.46 ; CONN2.P2-22 69.24,19.52 ; CONN2.P2-22 68.29,20.46 ; CONN2.P2-22 69.24,21.4
  G19 w0.635: CONN2.P2-11 79.4,21.4 ; CONN2.P2-11 78.45,20.46 ; CONN2.P2-11 80.34,20.46 ; CONN2.P2-11 79.4,19.52 ; CONN3.P2-12 139.15,21.4 ; CONN3.P2-12 138.21,20.46 ; CONN3.P2-12 140.1,20.46 ; CONN3.P2-12 139.15,19.52 ; CONN3.P4-23 129.94,17.92 ; CONN3.P4-23 128.99,16.98 ; CONN3.P4-23 128.99,18.86 ; CONN3.P4-23 128.05,17.92 ; CONN5.P4 318.85,13.84 ; CONN5.P4 318.85,11.46 ; CONN5.P4 317.66,12.65 ; CONN4.P2-13 198.92,21.4 ; CONN4.P2-13 198.92,19.52 ; CONN4.P2-13 199.86,20.46 ; CONN4.P2-13 197.97,20.46 ; 141.69,19.52 CONN3.P2-11 ; CONN3.P2-11 141.69,21.4 ; CONN3.P2-11 140.75,20.46 ; CONN3.P2-11 142.64,20.46 ; CONN5.P3 321.15,13.84 ; CONN5.P3 321.15,11.46 ; CONN5.P3 322.34,12.65 ; 8.53,17.92 CONN1.P4-21 ; CONN1.P4-21 9.47,16.98 ; CONN1.P4-21 10.42,17.92 ; CONN1.P4-21 9.47,18.86 ; 204,16.98 CONN4.P4-11 ; CONN4.P4-11 203.05,17.92 ; CONN4.P4-11 204.94,17.92 ; CONN4.P4-11 204,18.86 ; CONN1.P4-13 12.96,17.92 ; CONN1.P4-13 12.01,16.98 ; CONN1.P4-13 11.07,17.92 ; CONN1.P4-13 12.01,18.86 ; CONN2.P4-13 74.32,18.86 ; CONN2.P4-13 75.26,17.92 ; CONN2.P4-13 74.32,16.98 ; CONN2.P4-13 73.37,17.92 ; CONN4.P2-21 196.38,21.4 ; CONN4.P2-21 196.38,19.52 ; CONN4.P2-21 195.43,20.46 ; CONN4.P2-21 197.32,20.46 ; 128.99,19.52 CONN3.P2-23 ; CONN3.P2-23 128.99,21.4 ; CONN3.P2-23 129.94,20.46 ; CONN3.P2-23 128.05,20.46 ; CONN3.P4-12 139.15,18.86 ; CONN3.P4-12 138.21,17.92 ; CONN3.P4-12 139.15,16.98 ; CONN3.P4-12 140.1,17.92 ; CONN4.P4-23 192.24,17.92 ; CONN4.P4-23 191.3,16.98 ; CONN4.P4-23 190.35,17.92 ; CONN4.P4-23 191.3,18.86 ; CONN1.P4-23 4.39,18.86 ; CONN1.P4-23 4.39,16.98 ; CONN1.P4-23 3.45,17.92 ; CONN1.P4-23 5.34,17.92 ; 201.46,19.52 CONN4.P2-12 ; CONN4.P2-12 202.4,20.46 ; CONN4.P2-12 200.51,20.46 ; CONN4.P2-12 201.46,21.4 ; 200.51,17.92 CONN4.P4-12 ; CONN4.P4-12 201.46,16.98 ; CONN4.P4-12 202.4,17.92 ; CONN4.P4-12 201.46,18.86 ; 134.07,16.98 CONN3.P4-21 ; CONN3.P4-21 133.13,17.92 ; CONN3.P4-21 135.02,17.92 ; CONN3.P4-21 134.07,18.86 ; 5.99,20.46 CONN1.P2-22 ; CONN1.P2-22 6.93,21.4 ; CONN1.P2-22 7.88,20.46 ; CONN1.P2-22 6.93,19.52 ; CONN4.P2-22 194.78,20.46 ; CONN4.P2-22 192.89,20.46 ; CONN4.P2-22 193.84,21.4 ; CONN4.P2-22 193.84,19.52 ; 133.13,20.46 CONN3.P2-21 ; CONN3.P2-21 134.07,21.4 ; CONN3.P2-21 135.02,20.46 ; CONN3.P2-21 134.07,19.52 ; 135.67,17.92 CONN3.P4-13 ; CONN3.P4-13 136.61,18.86 ; CONN3.P4-13 136.61,16.98 ; CONN3.P4-13 137.56,17.92 ; CONN3.P4-22 132.48,17.92 ; CONN3.P4-22 131.53,18.86 ; CONN3.P4-22 130.59,17.92 ; CONN3.P4-22 131.53,16.98 ; CONN1.P2-13 12.96,20.46 ; CONN1.P2-13 12.01,21.4 ; CONN1.P2-13 12.01,19.52 ; CONN1.P2-13 11.07,20.46 ; 71.78,19.52 CONN2.P2-21 ; CONN2.P2-21 70.83,20.46 ; CONN2.P2-21 72.72,20.46 ; CONN2.P2-21 71.78,21.4 ; CONN2.P2-22 69.24,21.4 ; CONN2.P2-22 68.29,20.46 ; CONN2.P2-22 69.24,19.52 ; CONN2.P2-22 70.18,20.46 ; CONN4.P2-11 204.94,20.46 ; CONN4.P2-11 204,21.4 ; CONN4.P2-11 203.05,20.46 ; CONN4.P2-11 204,19.52 ; CONN1.P4-12 15.5,17.92 ; CONN1.P4-12 14.55,18.86 ; CONN1.P4-12 14.55,16.98 ; CONN1.P4-12 13.61,17.92 ; CONN1.P2-23 4.39,21.4 ; CONN1.P2-23 3.45,20.46 ; CONN1.P2-23 4.39,19.52 ; CONN1.P2-23 5.34,20.46 ; 65.75,17.92 CONN2.P4-23 ; CONN2.P4-23 67.64,17.92 ; CONN2.P4-23 66.7,16.98 ; CONN2.P4-23 66.7,18.86 ; 75.91,17.92 CONN2.P4-12 ; CONN2.P4-12 77.8,17.92 ; CONN2.P4-12 76.86,16.98 ; CONN2.P4-12 76.86,18.86 ; CONN2.P2-13 75.26,20.46 ; CONN2.P2-13 74.32,21.4 ; CONN2.P2-13 73.37,20.46 ; CONN2.P2-13 74.32,19.52 ; CONN2.P2-12 76.86,21.4 ; CONN2.P2-12 76.86,19.52 ; CONN2.P2-12 75.91,20.46 ; CONN2.P2-12 77.8,20.46 ; 8.53,20.46 CONN1.P2-21 ; CONN1.P2-21 9.47,19.52 ; CONN1.P2-21 9.47,21.4 ; CONN1.P2-21 10.42,20.46 ; CONN2.P2-23 67.64,20.46 ; CONN2.P2-23 65.75,20.46 ; CONN2.P2-23 66.7,19.52 ; CONN2.P2-23 66.7,21.4 ; CONN1.P2-12 15.5,20.46 ; CONN1.P2-12 14.55,21.4 ; CONN1.P2-12 13.61,20.46 ; CONN1.P2-12 14.55,19.52 ; CONN2.P4-22 69.24,18.86 ; CONN2.P4-22 70.18,17.92 ; CONN2.P4-22 68.29,17.92 ; CONN2.P4-22 69.24,16.98 ; CONN4.P4-21 197.32,17.92 ; CONN4.P4-21 196.38,18.86 ; CONN4.P4-21 195.43,17.92 ; CONN4.P4-21 196.38,16.98 ; CONN1.P4-22 6.93,18.86 ; CONN1.P4-22 6.93,16.98 ; CONN1.P4-22 5.99,17.92 ; CONN1.P4-22 7.88,17.92 ; 190.35,20.46 CONN4.P2-23 ; CONN4.P2-23 191.3,19.52 ; CONN4.P2-23 192.24,20.46 ; CONN4.P2-23 191.3,21.4 ; 130.59,20.46 CONN3.P2-22 ; CONN3.P2-22 131.53,21.4 ; CONN3.P2-22 132.48,20.46 ; CONN3.P2-22 131.53,19.52 ; 193.84,16.98 CONN4.P4-22 ; CONN4.P4-22 194.78,17.92 ; CONN4.P4-22 193.84,18.86 ; CONN4.P4-22 192.89,17.92 ; 140.75,17.92 CONN3.P4-11 ; CONN3.P4-11 141.69,18.86 ; CONN3.P4-11 141.69,16.98 ; CONN3.P4-11 142.64,17.92 ; 16.15,20.46 CONN1.P2-11 ; CONN1.P2-11 17.09,19.52 ; CONN1.P2-11 17.09,21.4 ; CONN1.P2-11 18.04,20.46 ; 71.78,16.98 CONN2.P4-21 ; CONN2.P4-21 71.78,18.86 ; CONN2.P4-21 72.72,17.92 ; CONN2.P4-21 70.83,17.92 ; CONN3.P2-13 136.61,21.4 ; CONN3.P2-13 135.67,20.46 ; CONN3.P2-13 137.56,20.46 ; CONN3.P2-13 136.61,19.52 ; 17.09,16.98 CONN1.P4-11 ; CONN1.P4-11 17.09,18.86 ; CONN1.P4-11 16.15,17.92 ; CONN1.P4-11 18.04,17.92 ; CONN2.P4-11 79.4,18.86 ; CONN2.P4-11 79.4,16.98 ; CONN2.P4-11 78.45,17.92 ; CONN2.P4-11 80.34,17.92 ; 197.97,17.92 CONN4.P4-13 ; CONN4.P4-13 199.86,17.92 ; CONN4.P4-13 198.92,16.98 ; CONN4.P4-13 198.92,18.86
  G21 w0.635: CONN1.P4-13 12.01,18.86 ; CONN1.P4-13 11.07,17.92 ; CONN1.P4-13 12.01,16.98 ; CONN1.P4-13 12.96,17.92 ; CONN5.P4 318.85,13.84 ; CONN5.P4 317.66,12.65 ; CONN5.P4 318.85,11.46 ; 128.05,20.46 CONN3.P2-23 ; CONN3.P2-23 129.94,20.46 ; CONN3.P2-23 128.99,19.52 ; CONN3.P2-23 128.99,21.4 ; CONN4.P4-23 192.24,17.92 ; CONN4.P4-23 191.3,18.86 ; CONN4.P4-23 190.35,17.92 ; CONN4.P4-23 191.3,16.98 ; 76.86,19.52 CONN2.P2-12 ; CONN2.P2-12 77.8,20.46 ; CONN2.P2-12 76.86,21.4 ; CONN2.P2-12 75.91,20.46 ; CONN2.P4-21 71.78,18.86 ; CONN2.P4-21 71.78,16.98 ; CONN2.P4-21 70.83,17.92 ; CONN2.P4-21 72.72,17.92 ; 74.32,16.98 CONN2.P4-13 ; CONN2.P4-13 73.37,17.92 ; CONN2.P4-13 74.32,18.86 ; CONN2.P4-13 75.26,17.92 ; 69.24,19.52 CONN2.P2-22 ; CONN2.P2-22 68.29,20.46 ; CONN2.P2-22 69.24,21.4 ; CONN2.P2-22 70.18,20.46 ; CONN1.P4-11 18.04,17.92 ; CONN1.P4-11 17.09,18.86 ; CONN1.P4-11 17.09,16.98 ; CONN1.P4-11 16.15,17.92 ; CONN4.P2-11 204,21.4 ; CONN4.P2-11 203.05,20.46 ; CONN4.P2-11 204,19.52 ; CONN4.P2-11 204.94,20.46 ; 12.01,19.52 CONN1.P2-13 ; CONN1.P2-13 12.01,21.4 ; CONN1.P2-13 12.96,20.46 ; CONN1.P2-13 11.07,20.46 ; 192.89,20.46 CONN4.P2-22 ; CONN4.P2-22 193.84,19.52 ; CONN4.P2-22 194.78,20.46 ; CONN4.P2-22 193.84,21.4 ; CONN2.P2-23 66.7,21.4 ; CONN2.P2-23 67.64,20.46 ; CONN2.P2-23 65.75,20.46 ; CONN2.P2-23 66.7,19.52 ; 201.46,19.52 CONN4.P2-12 ; CONN4.P2-12 201.46,21.4 ; CONN4.P2-12 200.51,20.46 ; CONN4.P2-12 202.4,20.46 ; 14.55,16.98 CONN1.P4-12 ; CONN1.P4-12 13.61,17.92 ; CONN1.P4-12 14.55,18.86 ; CONN1.P4-12 15.5,17.92 ; CONN4.P2-23 192.24,20.46 ; CONN4.P2-23 191.3,21.4 ; CONN4.P2-23 190.35,20.46 ; CONN4.P2-23 191.3,19.52 ; CONN1.P4-23 5.34,17.92 ; CONN1.P4-23 4.39,16.98 ; CONN1.P4-23 3.45,17.92 ; CONN1.P4-23 4.39,18.86 ; 130.59,20.46 CONN3.P2-22 ; CONN3.P2-22 131.53,19.52 ; CONN3.P2-22 132.48,20.46 ; CONN3.P2-22 131.53,21.4 ; CONN1.P2-12 15.5,20.46 ; CONN1.P2-12 14.55,19.52 ; CONN1.P2-12 13.61,20.46 ; CONN1.P2-12 14.55,21.4 ; 321.15,11.46 CONN5.P3 ; CONN5.P3 322.34,12.65 ; CONN5.P3 321.15,13.84 ; CONN1.P2-21 9.47,21.4 ; CONN1.P2-21 9.47,19.52 ; CONN1.P2-21 8.53,20.46 ; CONN1.P2-21 10.42,20.46 ; 131.53,16.98 CONN3.P4-22 ; CONN3.P4-22 131.53,18.86 ; CONN3.P4-22 132.48,17.92 ; CONN3.P4-22 130.59,17.92 ; 128.99,16.98 CONN3.P4-23 ; CONN3.P4-23 129.94,17.92 ; CONN3.P4-23 128.99,18.86 ; CONN3.P4-23 128.05,17.92 ; CONN4.P2-13 199.86,20.46 ; CONN4.P2-13 198.92,19.52 ; CONN4.P2-13 198.92,21.4 ; CONN4.P2-13 197.97,20.46 ; CONN2.P4-12 76.86,18.86 ; CONN2.P4-12 77.8,17.92 ; CONN2.P4-12 75.91,17.92 ; CONN2.P4-12 76.86,16.98 ; 195.43,17.92 CONN4.P4-21 ; CONN4.P4-21 196.38,18.86 ; CONN4.P4-21 196.38,16.98 ; CONN4.P4-21 197.32,17.92 ; 193.84,16.98 CONN4.P4-22 ; CONN4.P4-22 193.84,18.86 ; CONN4.P4-22 194.78,17.92 ; CONN4.P4-22 192.89,17.92 ; 17.09,19.52 CONN1.P2-11 ; CONN1.P2-11 18.04,20.46 ; CONN1.P2-11 17.09,21.4 ; CONN1.P2-11 16.15,20.46 ; 135.67,20.46 CONN3.P2-13 ; CONN3.P2-13 137.56,20.46 ; CONN3.P2-13 136.61,19.52 ; CONN3.P2-13 136.61,21.4 ; 201.46,16.98 CONN4.P4-12 ; CONN4.P4-12 200.51,17.92 ; CONN4.P4-12 201.46,18.86 ; CONN4.P4-12 202.4,17.92 ; CONN3.P4-21 135.02,17.92 ; CONN3.P4-21 133.13,17.92 ; CONN3.P4-21 134.07,18.86 ; CONN3.P4-21 134.07,16.98 ; 74.32,19.52 CONN2.P2-13 ; CONN2.P2-13 75.26,20.46 ; CONN2.P2-13 74.32,21.4 ; CONN2.P2-13 73.37,20.46 ; 198.92,16.98 CONN4.P4-13 ; CONN4.P4-13 197.97,17.92 ; CONN4.P4-13 199.86,17.92 ; CONN4.P4-13 198.92,18.86 ; 140.75,17.92 CONN3.P4-11 ; CONN3.P4-11 142.64,17.92 ; CONN3.P4-11 141.69,18.86 ; CONN3.P4-11 141.69,16.98 ; 135.67,17.92 CONN3.P4-13 ; CONN3.P4-13 136.61,16.98 ; CONN3.P4-13 136.61,18.86 ; CONN3.P4-13 137.56,17.92 ; CONN1.P2-22 7.88,20.46 ; CONN1.P2-22 5.99,20.46 ; CONN1.P2-22 6.93,21.4 ; CONN1.P2-22 6.93,19.52 ; 4.39,19.52 CONN1.P2-23 ; CONN1.P2-23 4.39,21.4 ; CONN1.P2-23 3.45,20.46 ; CONN1.P2-23 5.34,20.46 ; 79.4,19.52 CONN2.P2-11 ; CONN2.P2-11 79.4,21.4 ; CONN2.P2-11 80.34,20.46 ; CONN2.P2-11 78.45,20.46 ; 6.93,16.98 CONN1.P4-22 ; CONN1.P4-22 7.88,17.92 ; CONN1.P4-22 6.93,18.86 ; CONN1.P4-22 5.99,17.92 ; CONN1.P4-21 9.47,18.86 ; CONN1.P4-21 10.42,17.92 ; CONN1.P4-21 8.53,17.92 ; CONN1.P4-21 9.47,16.98 ; CONN2.P4-22 70.18,17.92 ; CONN2.P4-22 69.24,18.86 ; CONN2.P4-22 69.24,16.98 ; CONN2.P4-22 68.29,17.92 ; 78.45,17.92 CONN2.P4-11 ; CONN2.P4-11 79.4,16.98 ; CONN2.P4-11 79.4,18.86 ; CONN2.P4-11 80.34,17.92 ; 133.13,20.46 CONN3.P2-21 ; CONN3.P2-21 135.02,20.46 ; CONN3.P2-21 134.07,21.4 ; CONN3.P2-21 134.07,19.52 ; 195.43,20.46 CONN4.P2-21 ; CONN4.P2-21 196.38,21.4 ; CONN4.P2-21 196.38,19.52 ; CONN4.P2-21 197.32,20.46 ; 70.83,20.46 CONN2.P2-21 ; CONN2.P2-21 71.78,21.4 ; CONN2.P2-21 71.78,19.52 ; CONN2.P2-21 72.72,20.46 ; 139.15,19.52 CONN3.P2-12 ; CONN3.P2-12 138.21,20.46 ; CONN3.P2-12 140.1,20.46 ; CONN3.P2-12 139.15,21.4 ; 141.69,19.52 CONN3.P2-11 ; CONN3.P2-11 141.69,21.4 ; CONN3.P2-11 140.75,20.46 ; CONN3.P2-11 142.64,20.46 ; CONN3.P4-12 139.15,18.86 ; CONN3.P4-12 140.1,17.92 ; CONN3.P4-12 138.21,17.92 ; CONN3.P4-12 139.15,16.98 ; CONN4.P4-11 204,18.86 ; CONN4.P4-11 203.05,17.92 ; CONN4.P4-11 204,16.98 ; CONN4.P4-11 204.94,17.92 ; CONN2.P4-23 67.64,17.92 ; CONN2.P4-23 66.7,16.98 ; CONN2.P4-23 65.75,17.92 ; CONN2.P4-23 66.7,18.86
  BOTTOM w0.381: v2(163.07,26.16) 163.32,25.91 R16.1 ; R19.2 v2(171.2,26.16) ; v2(10.16,50.55) 10.11,50.49 C6.2 ; C7.2 v2(260.35,48.51) ; C14.2 384.5,27.38 v2(385.06,27.94) ; C2.2 112.83,55.83 v2(112.58,56.08) ; R4.1 v2(41.15,26.16) ; v2(12.39,29.16) 12.65,28.9 C12.2 ; v2(127.2,55.88) 127.45,55.63 C3.2 ; R11.1 v2(104.14,26.42) ; v2(330.15,28.9) 330.4,28.65 C13.2 ; C16.2 v2(381.25,22.35) ; R10.1 101.8,25.35 v2(101.85,25.4) ; R3.1 v2(38.61,26.16) ; R23.1 228.09,25.91 v2(228.35,26.16) ; R8.1 v2(48.51,26.16) ; R24.1 v2(229.62,26.16) ; R5.1 v2(42.16,26.16) ; R18.1 v2(167.39,26.16) ; R7.2 46.99,25.91 46.97,25.93 46.97,26.11 v2(47.02,26.16) ; C4.2 263.09,55.83 v2(263.34,56.08) ; C18.2 v2(246.13,3.81) ; v2(12.9,54.16) 12.65,54.41 C1.2 ; C11.2 v2(322.13,35.51) ; C8.2 v2(387.4,47.81) ; v2(259.33,11.68) 259.53,11.88 C17.2 ; v2(226.31,26.16) 225.81,25.65 R22.1 ; R25.2 v2(234.19,26.16) ; v2(119.13,35.25) 119.38,35.51 C10.2 ; R26.1 v2(235.46,26.16) ; C9.2 v2(5.08,36.32) ; C5.2 380.8,55.63 v2(380.55,55.88) ; R20.1 v2(173.23,26.16) ; R17.1 v2(165.86,26.42) ; R12.1 v2(105.16,26.16) ; R14.1 v2(110.74,26.42) ; C15.2 v2(120.85,20.63) ; R13.2 v2(108.97,26.16)
  BOTTOM w0.635: 195.43,17.92 CONN4.P4-21 ; CONN4.P4-21 197.32,17.92 ; CONN4.P4-21 196.38,16.98 ; CONN4.P4-21 196.38,18.86 ; CONN2.P4-23 67.64,17.92 ; CONN2.P4-23 66.7,16.98 ; CONN2.P4-23 66.7,18.86 ; CONN2.P4-23 65.75,17.92 ; CONN4.P2-12 201.46,21.4 ; CONN4.P2-12 201.46,19.52 ; CONN4.P2-12 200.51,20.46 ; CONN4.P2-12 202.4,20.46 ; CONN4.P4-22 194.78,17.92 ; CONN4.P4-22 192.89,17.92 ; CONN4.P4-22 193.84,18.86 ; CONN4.P4-22 193.84,16.98 ; 135.67,17.92 CONN3.P4-13 ; CONN3.P4-13 137.56,17.92 ; CONN3.P4-13 136.61,18.86 ; CONN3.P4-13 136.61,16.98 ; CONN4.P2-11 204,21.4 ; CONN4.P2-11 203.05,20.46 ; CONN4.P2-11 204,19.52 ; CONN4.P2-11 204.94,20.46 ; 12.01,16.98 CONN1.P4-13 ; CONN1.P4-13 12.01,18.86 ; CONN1.P4-13 12.96,17.92 ; CONN1.P4-13 11.07,17.92 ; 74.32,19.52 CONN2.P2-13 ; CONN2.P2-13 74.32,21.4 ; CONN2.P2-13 75.26,20.46 ; CONN2.P2-13 73.37,20.46 ; 14.55,16.98 CONN1.P4-12 ; CONN1.P4-12 14.55,18.86 ; CONN1.P4-12 15.5,17.92 ; CONN1.P4-12 13.61,17.92 ; 71.78,19.52 CONN2.P2-21 ; CONN2.P2-21 71.78,21.4 ; CONN2.P2-21 70.83,20.46 ; CONN2.P2-21 72.72,20.46 ; 318.85,11.46 CONN5.P4 ; CONN5.P4 318.85,13.84 ; CONN5.P4 317.66,12.65 ; CONN1.P4-11 17.09,18.86 ; CONN1.P4-11 16.15,17.92 ; CONN1.P4-11 18.04,17.92 ; CONN1.P4-11 17.09,16.98 ; 75.91,17.92 CONN2.P4-12 ; CONN2.P4-12 77.8,17.92 ; CONN2.P4-12 76.86,16.98 ; CONN2.P4-12 76.86,18.86 ; CONN2.P4-11 80.34,17.92 ; CONN2.P4-11 79.4,16.98 ; CONN2.P4-11 79.4,18.86 ; CONN2.P4-11 78.45,17.92 ; CONN1.P4-23 5.34,17.92 ; CONN1.P4-23 4.39,18.86 ; CONN1.P4-23 4.39,16.98 ; CONN1.P4-23 3.45,17.92 ; CONN2.P2-12 76.86,21.4 ; CONN2.P2-12 75.91,20.46 ; CONN2.P2-12 77.8,20.46 ; CONN2.P2-12 76.86,19.52 ; 79.4,19.52 CONN2.P2-11 ; CONN2.P2-11 79.4,21.4 ; CONN2.P2-11 80.34,20.46 ; CONN2.P2-11 78.45,20.46 ; CONN3.P2-12 139.15,21.4 ; CONN3.P2-12 139.15,19.52 ; CONN3.P2-12 140.1,20.46 ; CONN3.P2-12 138.21,20.46 ; 16.15,20.46 CONN1.P2-11 ; CONN1.P2-11 18.04,20.46 ; CONN1.P2-11 17.09,19.52 ; CONN1.P2-11 17.09,21.4 ; 12.01,19.52 CONN1.P2-13 ; CONN1.P2-13 11.07,20.46 ; CONN1.P2-13 12.96,20.46 ; CONN1.P2-13 12.01,21.4 ; 201.46,16.98 CONN4.P4-12 ; CONN4.P4-12 201.46,18.86 ; CONN4.P4-12 200.51,17.92 ; CONN4.P4-12 202.4,17.92 ; CONN3.P4-21 134.07,18.86 ; CONN3.P4-21 134.07,16.98 ; CONN3.P4-21 133.13,17.92 ; CONN3.P4-21 135.02,17.92 ; CONN3.P2-23 128.99,21.4 ; CONN3.P2-23 129.94,20.46 ; CONN3.P2-23 128.99,19.52 ; CONN3.P2-23 128.05,20.46 ; 190.35,17.92 CONN4.P4-23 ; CONN4.P4-23 192.24,17.92 ; CONN4.P4-23 191.3,18.86 ; CONN4.P4-23 191.3,16.98 ; CONN3.P4-22 131.53,18.86 ; CONN3.P4-22 131.53,16.98 ; CONN3.P4-22 132.48,17.92 ; CONN3.P4-22 130.59,17.92 ; 68.29,17.92 CONN2.P4-22 ; CONN2.P4-22 70.18,17.92 ; CONN2.P4-22 69.24,18.86 ; CONN2.P4-22 69.24,16.98 ; 190.35,20.46 CONN4.P2-23 ; CONN4.P2-23 192.24,20.46 ; CONN4.P2-23 191.3,19.52 ; CONN4.P2-23 191.3,21.4 ; CONN3.P2-13 136.61,21.4 ; CONN3.P2-13 135.67,20.46 ; CONN3.P2-13 137.56,20.46 ; CONN3.P2-13 136.61,19.52 ; CONN4.P4-11 204.94,17.92 ; CONN4.P4-11 204,16.98 ; CONN4.P4-11 203.05,17.92 ; CONN4.P4-11 204,18.86 ; CONN3.P4-11 142.64,17.92 ; CONN3.P4-11 141.69,16.98 ; CONN3.P4-11 140.75,17.92 ; CONN3.P4-11 141.69,18.86 ; CONN4.P2-21 196.38,21.4 ; CONN4.P2-21 196.38,19.52 ; CONN4.P2-21 197.32,20.46 ; CONN4.P2-21 195.43,20.46 ; CONN1.P2-22 7.88,20.46 ; CONN1.P2-22 6.93,21.4 ; CONN1.P2-22 6.93,19.52 ; CONN1.P2-22 5.99,20.46 ; CONN2.P4-13 75.26,17.92 ; CONN2.P4-13 74.32,18.86 ; CONN2.P4-13 74.32,16.98 ; CONN2.P4-13 73.37,17.92 ; CONN2.P4-21 71.78,18.86 ; CONN2.P4-21 70.83,17.92 ; CONN2.P4-21 72.72,17.92 ; CONN2.P4-21 71.78,16.98 ; 8.53,20.46 CONN1.P2-21 ; CONN1.P2-21 9.47,21.4 ; CONN1.P2-21 10.42,20.46 ; CONN1.P2-21 9.47,19.52 ; CONN3.P2-21 135.02,20.46 ; CONN3.P2-21 133.13,20.46 ; CONN3.P2-21 134.07,21.4 ; CONN3.P2-21 134.07,19.52 ; CONN4.P2-13 199.86,20.46 ; CONN4.P2-13 198.92,19.52 ; CONN4.P2-13 198.92,21.4 ; CONN4.P2-13 197.97,20.46 ; CONN2.P2-23 66.7,21.4 ; CONN2.P2-23 65.75,20.46 ; CONN2.P2-23 66.7,19.52 ; CONN2.P2-23 67.64,20.46 ; CONN4.P2-22 194.78,20.46 ; CONN4.P2-22 193.84,19.52 ; CONN4.P2-22 192.89,20.46 ; CONN4.P2-22 193.84,21.4 ; 3.45,20.46 CONN1.P2-23 ; CONN1.P2-23 5.34,20.46 ; CONN1.P2-23 4.39,19.52 ; CONN1.P2-23 4.39,21.4 ; 68.29,20.46 CONN2.P2-22 ; CONN2.P2-22 69.24,19.52 ; CONN2.P2-22 70.18,20.46 ; CONN2.P2-22 69.24,21.4 ; 197.97,17.92 CONN4.P4-13 ; CONN4.P4-13 199.86,17.92 ; CONN4.P4-13 198.92,18.86 ; CONN4.P4-13 198.92,16.98 ; 128.05,17.92 CONN3.P4-23 ; CONN3.P4-23 128.99,16.98 ; CONN3.P4-23 128.99,18.86 ; CONN3.P4-23 129.94,17.92 ; CONN3.P2-11 142.64,20.46 ; CONN3.P2-11 141.69,19.52 ; CONN3.P2-11 141.69,21.4 ; CONN3.P2-11 140.75,20.46 ; CONN3.P2-22 131.53,21.4 ; CONN3.P2-22 130.59,20.46 ; CONN3.P2-22 132.48,20.46 ; CONN3.P2-22 131.53,19.52 ; 9.47,16.98 CONN1.P4-21 ; CONN1.P4-21 9.47,18.86 ; CONN1.P4-21 8.53,17.92 ; CONN1.P4-21 10.42,17.92 ; CONN5.P3 322.34,12.65 ; CONN5.P3 321.15,13.84 ; CONN5.P3 321.15,11.46 ; CONN3.P4-12 139.15,18.86 ; CONN3.P4-12 138.21,17.92 ; CONN3.P4-12 140.1,17.92 ; CONN3.P4-12 139.15,16.98 ; CONN1.P4-22 6.93,18.86 ; CONN1.P4-22 6.93,16.98 ; CONN1.P4-22 5.99,17.92 ; CONN1.P4-22 7.88,17.92 ; CONN1.P2-12 15.5,20.46 ; CONN1.P2-12 14.55,21.4 ; CONN1.P2-12 13.61,20.46 ; CONN1.P2-12 14.55,19.52
  vias: v1(21.84,26.92) v1(27.69,28.96) v1(33.53,41.4) v1(58.93,49.78) v1(63.5,35.31) v1(88.14,35.05) v1(97.54,50.29) v1(145.03,49.02) v1(160.53,50.55) v1(191.52,51.31) v1(223.77,51.31) v1(276.61,39.88) v1(293.12,49.02) v1(302.77,39.37) v1(319.79,48.26) v1(338.33,48.26) v2(1.3,49.78) v2(1.3,46.23) v2(1.3,40.64) v2(1.3,36.83) v2(1.3,33.27) v2(1.3,22.35) v2(1.3,18.03) v2(1.3,14.48) v2(1.3,10.92) v2(1.3,7.11) v2(1.3,2.29) v2(5.08,40.64) v2(5.84,13.72) v2(5.84,1.3) v2(6.35,7.11) v2(10.16,58.67) v2(11.94,1.3) v2(12.7,58.67) v2(13.21,12.95) v2(15.49,58.67) v2(15.75,54.86) v2(15.75,7.62) v2(17.02,25.65) v2(17.53,41.4) v2(17.78,1.3) v2(19.05,58.67) v2(20.07,34.54) v2(22.35,51.31) v2(22.86,58.67) v2(24.89,13.21) v2(24.89,1.3) v2(25.15,43.69) v2(25.4,7.11) v2(26.67,58.67) v2(28.45,24.13) v2(29.72,31.24) v2(29.72,1.3) v2(30.73,58.67) v2(32.51,12.95) v2(33.02,22.86) v2(34.54,58.67) v2(34.8,1.3) v2(35.05,6.86) v2(35.56,13.46) v2(36.07,34.29) v2(37.59,58.67) v2(38.86,53.09) v2(41.15,58.67) v2(42.42,1.3) v2(42.93,13.46) v2(44.7,10.67) v2(44.96,48.26) v2(44.96,7.37) v2(45.21,58.67) v2(45.47,38.1) v2(45.72,31.75) v2(49.02,54.36) v2(50.04,58.67) v2(50.55,1.3) v2(50.8,13.72) v2(51.82,29.72) v2(53.85,20.07) v2(55.12,58.67) v2(57.4,32) v2(57.4,6.6) v2(57.66,13.72) v2(58.17,24.13) v2(58.42,1.3) v2(59.18,20.32) v2(59.69,58.67) v2(61.47,38.1) v2(62.23,53.85) v2(62.99,23.11) v2(63.75,11.43) v2(64.26,58.67) v2(64.52,1.3) v2(65.02,29.46) v2(67.56,24.38) v2(67.82,48.51) v2(69.6,58.67) v2(70.36,1.3) v2(71.37,32.26) v2(72.64,23.11) v2(73.41,44.45) v2(74.42,58.67) v2(76.45,29.46) v2(76.96,52.83) v2(77.22,1.3) v2(77.47,12.45) v2(78.49,7.87) v2(79.25,24.38) v2(79.5,58.67) v2(81.53,48.77) v2(82.3,32) v2(82.55,1.3) v2(83.06,37.85) v2(84.84,58.67) v2(85.34,54.1) v2(85.34,23.11) v2(86.87,12.19) v2(87.38,24.38) v2(87.63,1.3) v2(89.66,58.67) v2(90.42,7.37) v2(91.44,23.62) v2(92.96,54.61) v2(93.22,1.3) v2(93.47,32.26) v2(95,58.67) v2(96.52,45.21) v2(97.28,12.45) v2(99.06,1.3) v2(99.57,38.1) v2(100.08,13.97) v2(100.08,8.89) v2(100.33,58.67) v2(101.85,54.1) v2(103.63,32.26) v2(104.14,1.3) v2(105.41,38.86) v2(105.92,58.67) v2(107.95,54.1) v2(109.98,1.3) v2(110.24,10.41) v2(110.49,43.94) v2(112.01,58.67) v2(112.27,50.8) v2(113.28,36.83) v2(114.81,30.99) v2(114.81,16.26) v2(115.06,23.88) v2(115.06,21.08) v2(116.08,1.3) v2(116.84,17.02) v2(119.38,9.65) v2(121.41,34.29) v2(122.43,44.96) v2(122.68,1.3) v2(124.46,38.35) v2(124.71,17.78) v2(124.97,58.67) v2(126.49,28.96) v2(128.52,58.67) v2(128.52,41.4) v2(129.29,24.64) v2(130.05,10.67) v2(131.57,26.92) v2(131.57,1.52) v2(132.33,58.67) v2(134.11,53.59) v2(135.64,44.45) v2(135.89,48.51) v2(135.89,34.8) v2(136.65,24.38) v2(136.91,58.67) v2(139.7,12.45) v2(139.7,1.3) v2(140.97,55.12) v2(141.48,41.15) v2(142.24,58.67) v2(144.27,6.6) v2(146.05,1.3) v2(146.3,58.67) v2(148.59,24.89) v2(151.38,56.64) v2(151.89,41.15) v2(152.4,58.67) v2(152.91,1.3) v2(154.94,34.8) v2(156.46,24.38) v2(158.24,58.67) v2(159.26,55.63) v2(161.04,7.62) v2(161.29,1.3) v2(163.83,34.29) v2(164.34,58.67) v2(164.34,56.13) v2(169.42,41.15) v2(169.67,1.3) v2(171.2,58.67) v2(171.7,54.36) v2(171.96,43.18) v2(172.72,9.4) v2(176.78,1.3) v2(177.04,58.67) v2(177.8,54.36) v2(180.59,34.8) v2(181.1,18.8) v2(183.39,58.67) v2(183.64,11.68) v2(184.91,1.3) v2(185.17,22.61) v2(186.18,40.89) v2(187.45,54.1) v2(187.96,25.4) v2(189.48,23.88) v2(190.75,58.67) v2(192.53,1.3) v2(192.79,13.21) v2(195.07,24.89) v2(196.34,52.32) v2(196.34,34.8) v2(198.37,1.3) v2(198.63,58.67) v2(198.88,6.35) v2(199.64,23.11) v2(201.93,55.12) v2(202.18,25.65) v2(203.71,1.3) v2(204.47,58.67) v2(204.47,35.05) v2(206.76,41.15) v2(207.77,1.3) v2(208.28,12.19) v2(208.53,24.64) v2(210.31,58.67) v2(211.33,1.3) v2(213.11,34.54) v2(213.61,25.65) v2(214.38,23.62) v2(215.14,58.67) v2(215.65,1.3) v2(216.15,41.4) v2(218.69,35.05) v2(218.69,25.15) v2(218.95,52.83) v2(220.47,1.3) v2(220.98,58.67) v2(221.74,14.22) v2(221.74,7.62) v2(224.54,14.22) v2(225.04,1.3) v2(226.57,58.67) v2(228.6,1.3) v2(228.85,14.22) v2(229.87,34.29) v2(230.12,52.32) v2(231.9,58.67) v2(232.66,1.3) v2(233.43,12.95) v2(233.43,11.43) v2(235.71,44.96) v2(235.97,1.3) v2(238,58.67) v2(239.01,10.67) v2(239.27,53.85) v2(239.27,27.94) v2(240.28,1.3) v2(240.54,34.29) v2(241.05,12.95) v2(241.55,18.03) v2(241.81,39.37) v2(241.81,20.07) v2(242.06,27.94) v2(243.84,58.67) v2(244.09,1.3) v2(245.11,8.13) v2(245.87,27.94) v2(246.13,12.19) v2(247.65,39.62) v2(247.65,1.3) v2(248.16,27.94) v2(248.92,58.67) v2(249.17,19.81) v2(249.68,15.49) v2(250.95,1.3) v2(252.98,16.51) v2(253.75,41.91) v2(255.78,32.51) v2(256.79,12.95) v2(258.83,33.27) v2(259.33,28.96) v2(261.11,58.67) v2(261.37,1.3) v2(262.38,25.65) v2(262.89,8.64) v2(263.09,2.59) v2(263.65,27.94) v2(264.41,42.93) v2(264.67,1.3) v2(265.68,58.67) v2(266.45,5.84) v2(268.22,54.36) v2(269.24,3.81) v2(270,33.53) v2(270,1.3) v2(270.76,58.67) v2(271.53,45.21) v2(272.8,49.78) v2(274.83,20.83) v2(275.59,1.3) v2(276.35,31.5) v2(276.61,58.67) v2(277.37,4.06) v2(277.88,21.08) v2(278.89,47.5) v2(281.18,54.61) v2(281.18,20.07) v2(282.45,32.51) v2(282.7,58.67) v2(282.7,24.38) v2(283.21,1.3) v2(284.99,16.26) v2(285.5,3.81) v2(286.26,38.61) v2(286.51,46.99) v2(287.78,58.67) v2(287.78,13.46) v2(291.08,1.3) v2(291.59,12.19) v2(292.61,54.36) v2(293.37,58.67) v2(293.62,9.65) v2(293.88,5.84) v2(295.91,42.42) v2(295.91,6.86) v2(296.42,1.3) v2(297.69,15.75) v2(299.21,58.67) v2(301.5,51.31) v2(303.28,31.5) v2(303.53,1.3) v2(304.04,20.07) v2(304.04,7.11) v2(304.55,45.21) v2(304.8,58.67) v2(307.59,26.42) v2(308.36,11.68) v2(309.37,1.3) v2(309.63,58.67) v2(310.9,18.03) v2(311.91,38.86) v2(312.17,33.27) v2(313.44,47.75) v2(313.44,1.3) v2(314.2,58.67) v2(314.45,53.09) v2(316.99,1.3) v2(317.5,39.12) v2(318.01,58.67) v2(320.04,54.61) v2(320.55,1.3) v2(322.33,58.67) v2(324.1,1.3) v2(325.63,41.66) v2(326.39,1.3) v2(327.15,50.8) v2(327.66,58.67) v2(328.17,54.61) v2(328.17,19.05) v2(329.69,1.3) v2(332.23,58.67) v2(332.23,45.47) v2(332.74,1.3) v2(334.52,36.07) v2(334.52,13.72) v2(335.79,1.3) v2(336.3,26.42) v2(337.31,53.59) v2(337.31,18.8) v2(337.57,58.67) v2(338.58,9.14) v2(339.34,1.3) v2(339.85,41.4) v2(341.38,5.59) v2(342.65,35.05) v2(342.9,1.3) v2(344.68,45.21) v2(344.93,58.67) v2(344.93,28.7) v2(346.2,51.82) v2(346.71,12.45) v2(346.71,8.38) v2(346.71,2.79) v2(350.27,16.28) v2(350.77,20.32) v2(351.03,58.67) v2(352.04,27.69) v2(354.08,51.56) v2(355.09,16.31) v2(356.87,58.67) v2(357.12,21.34) v2(359.92,53.85) v2(360.93,16.28) v2(362.97,58.67) v2(362.97,47.75) v2(364.49,38.86) v2(366.27,16.28) v2(369.32,58.67) v2(369.57,29.72) v2(370.59,51.56) v2(371.6,16.28) v2(374.14,22.86) v2(374.65,58.67) v2(376.17,16.28) v2(377.95,53.34) v2(378.71,47.75) v2(379.98,16.28) v2(380.49,58.67) v2(382.78,16.28) v2(384.05,40.39) v2(384.56,33.02) v2(390.65,27.43) v2(391.67,50.04) v2(391.67,46.99) v2(391.67,43.43) v2(391.67,39.88) v2(391.67,33.78) v2(391.67,29.21) v2(391.67,25.4)
